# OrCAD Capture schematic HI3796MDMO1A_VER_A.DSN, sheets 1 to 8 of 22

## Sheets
1 SHEET_01
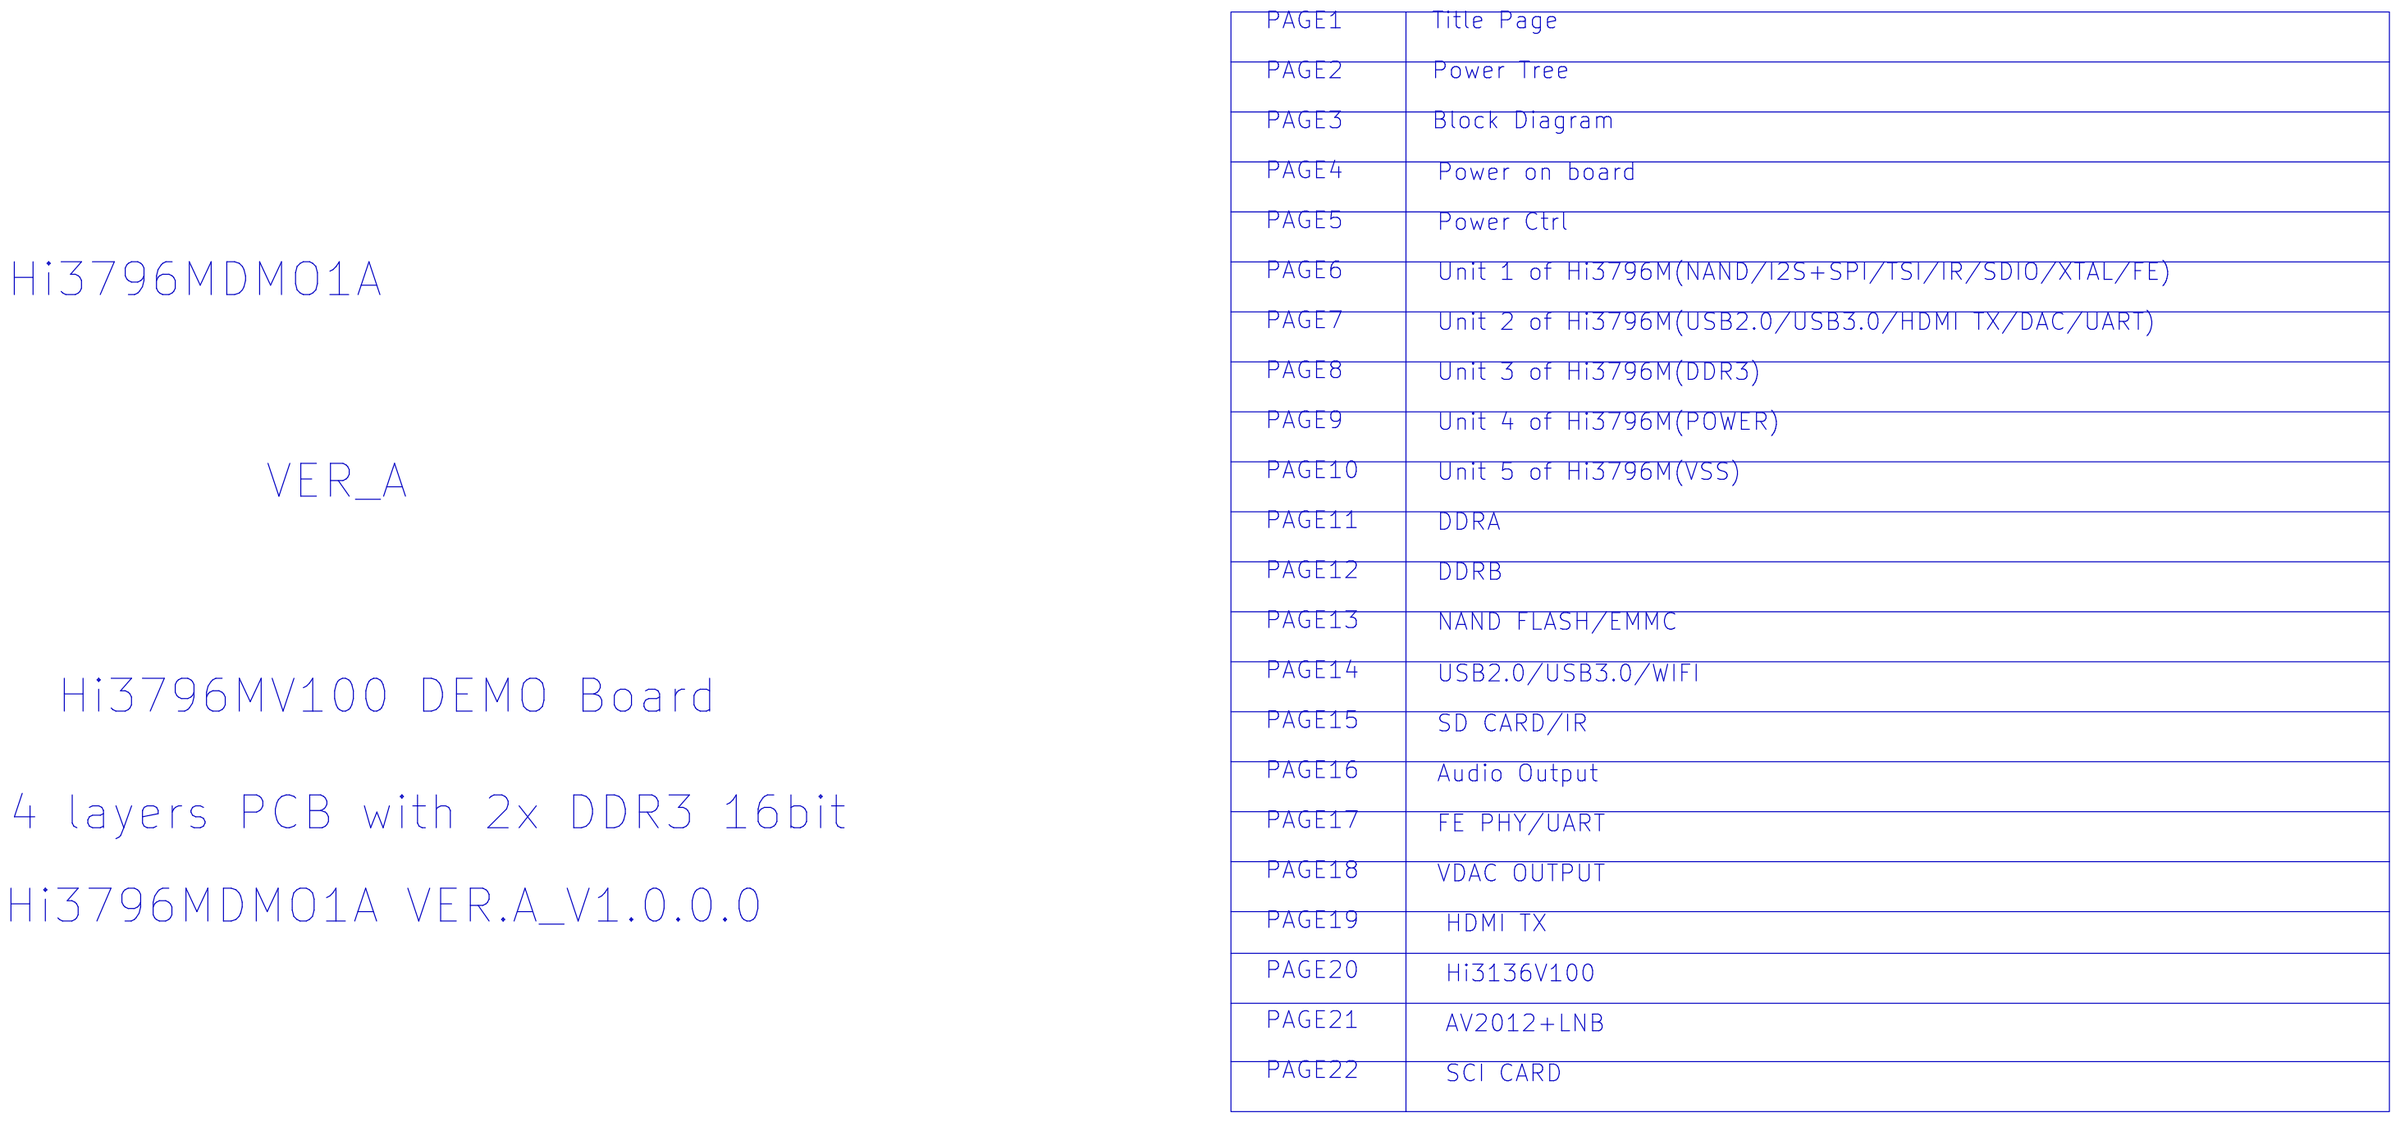
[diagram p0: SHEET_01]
2 SHEET_02
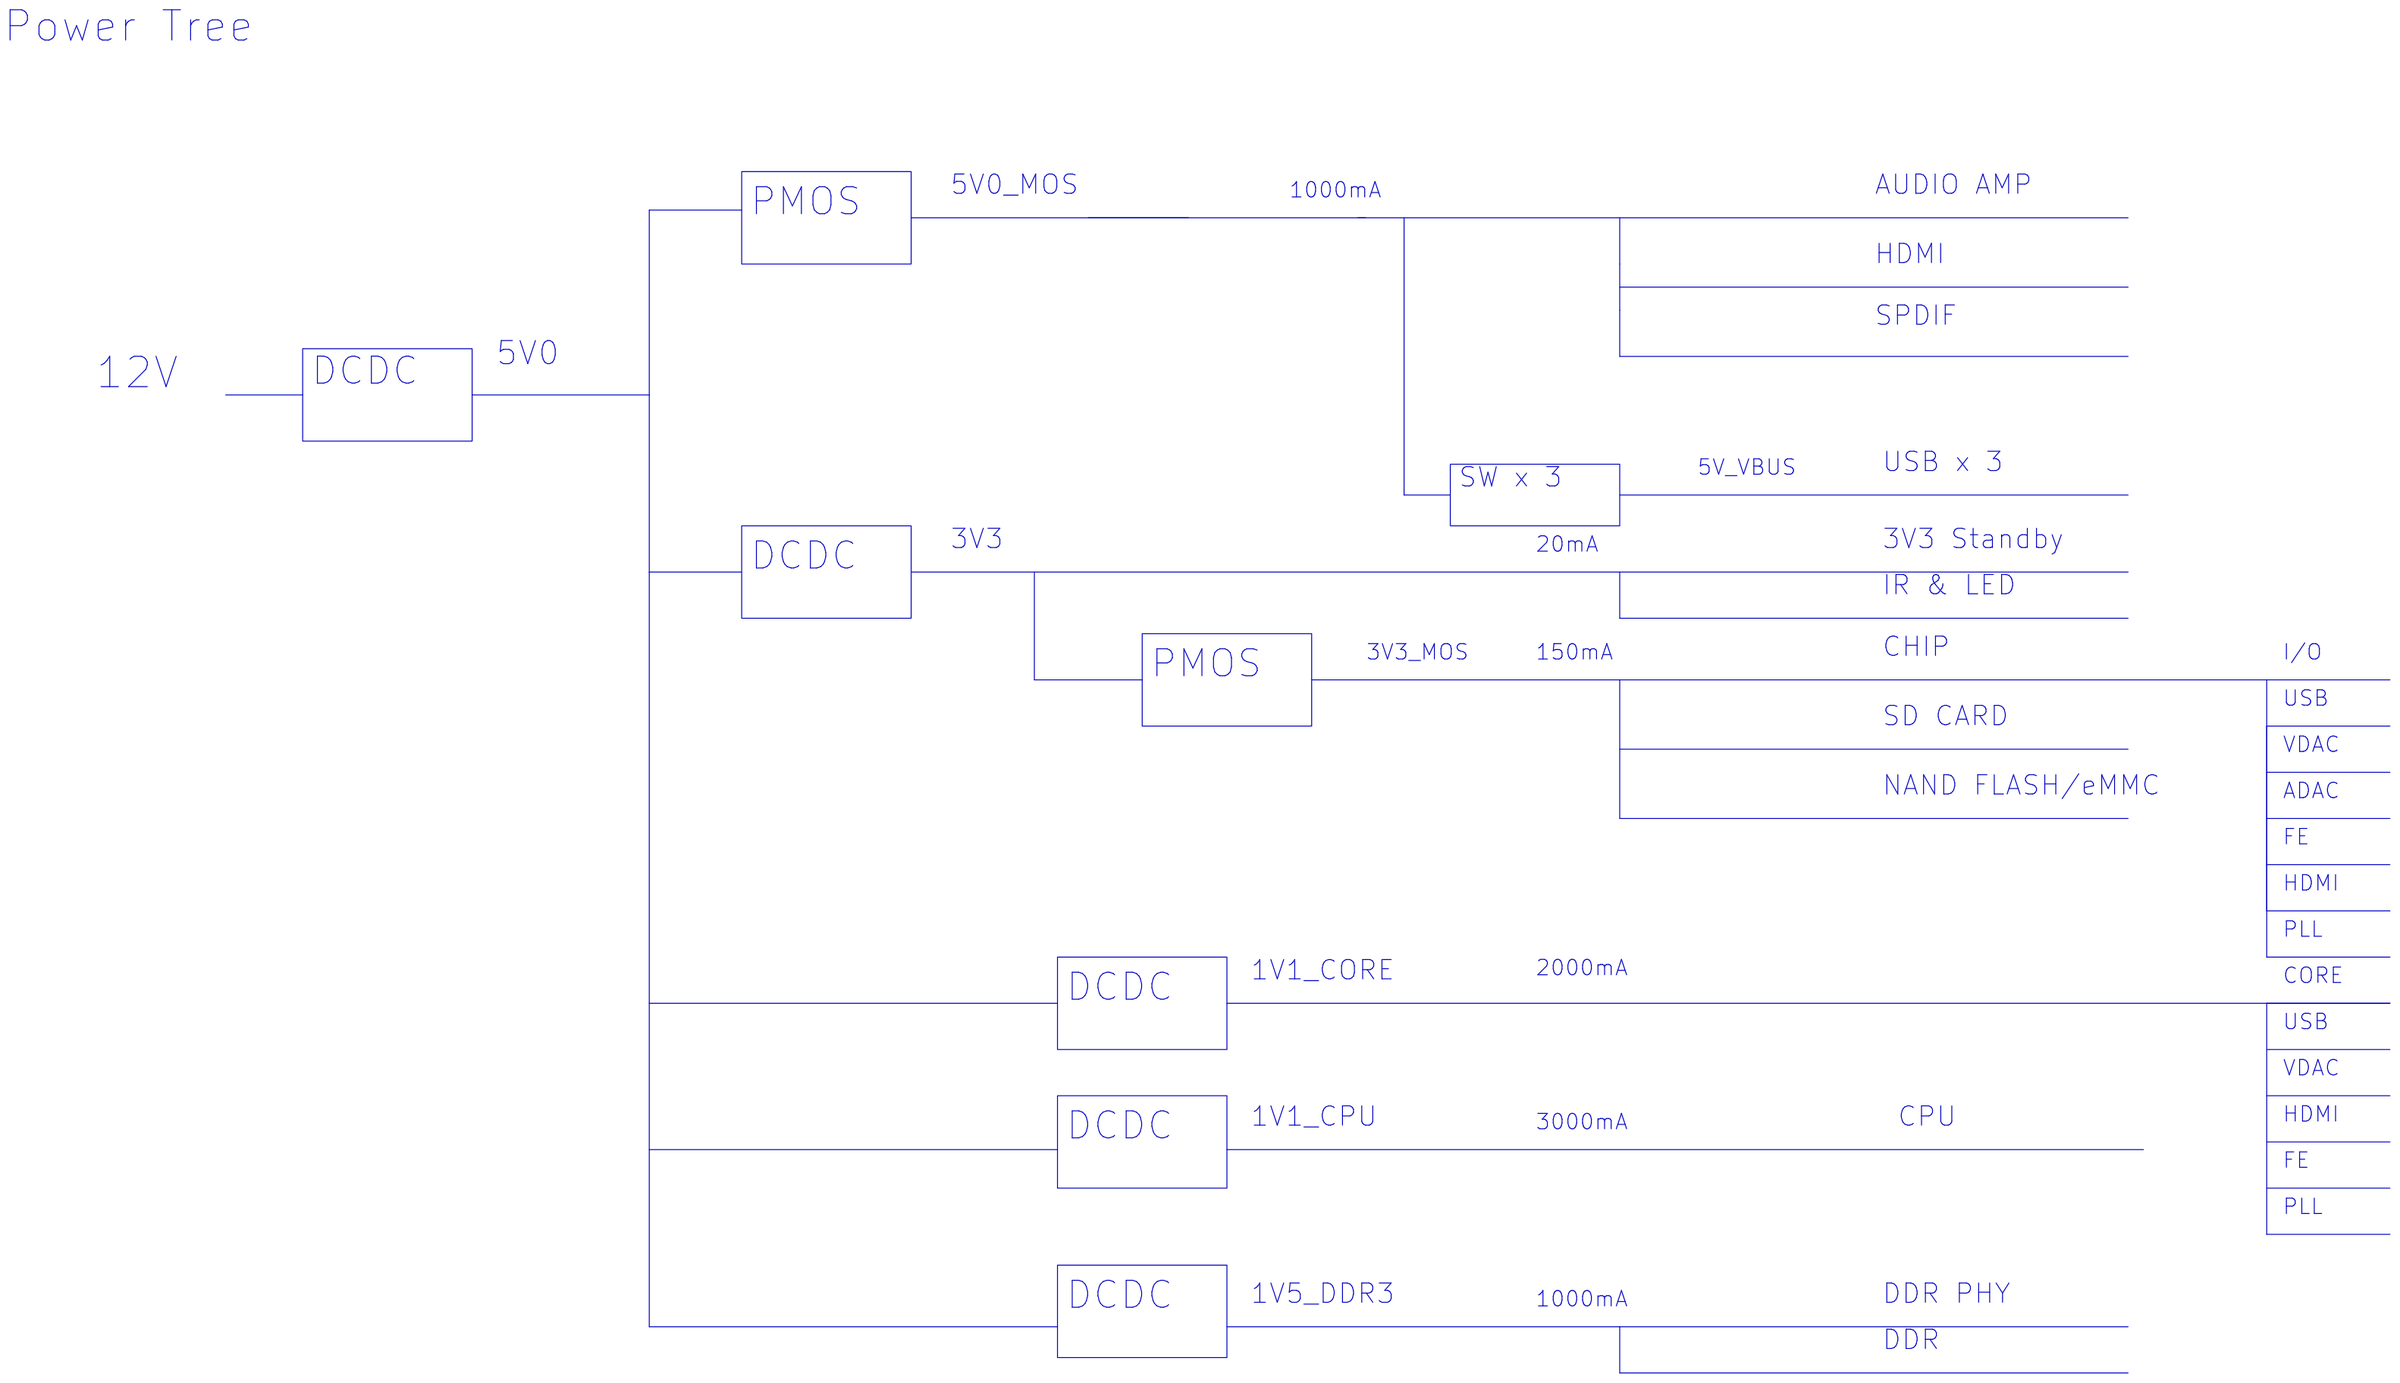
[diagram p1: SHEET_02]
3 SHEET_03: size B
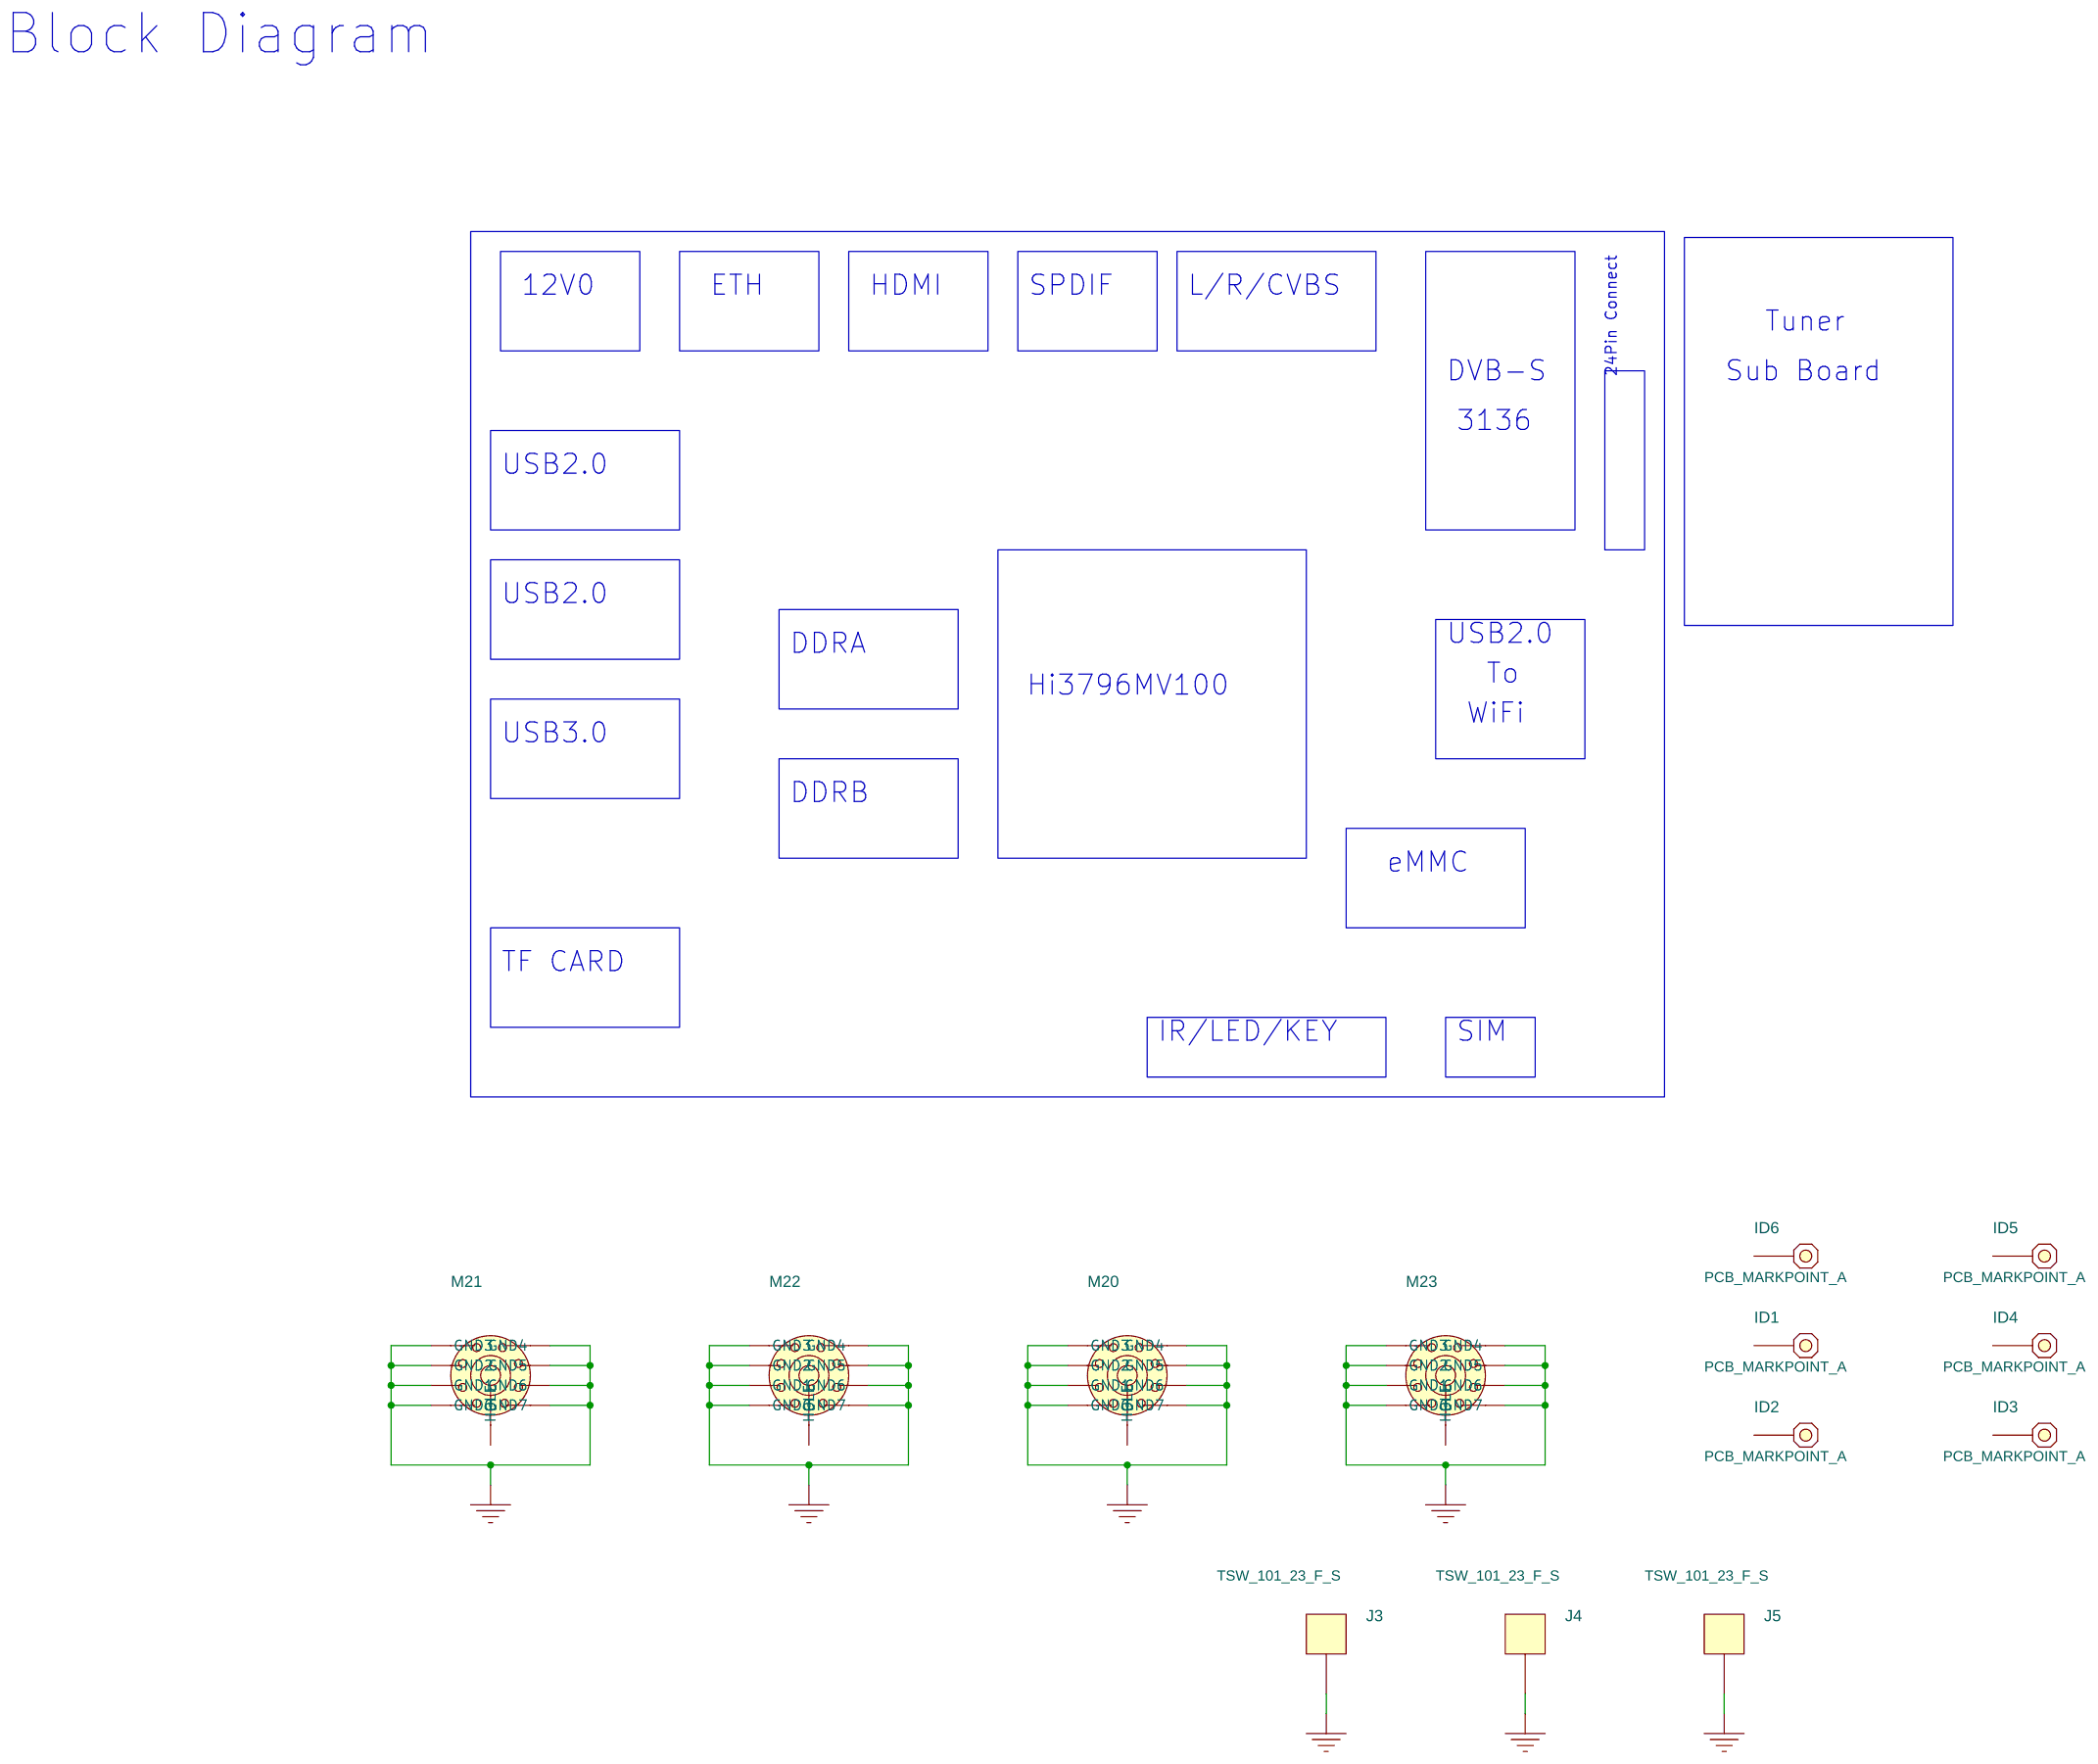
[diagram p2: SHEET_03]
4 SHEET_04: size Custom
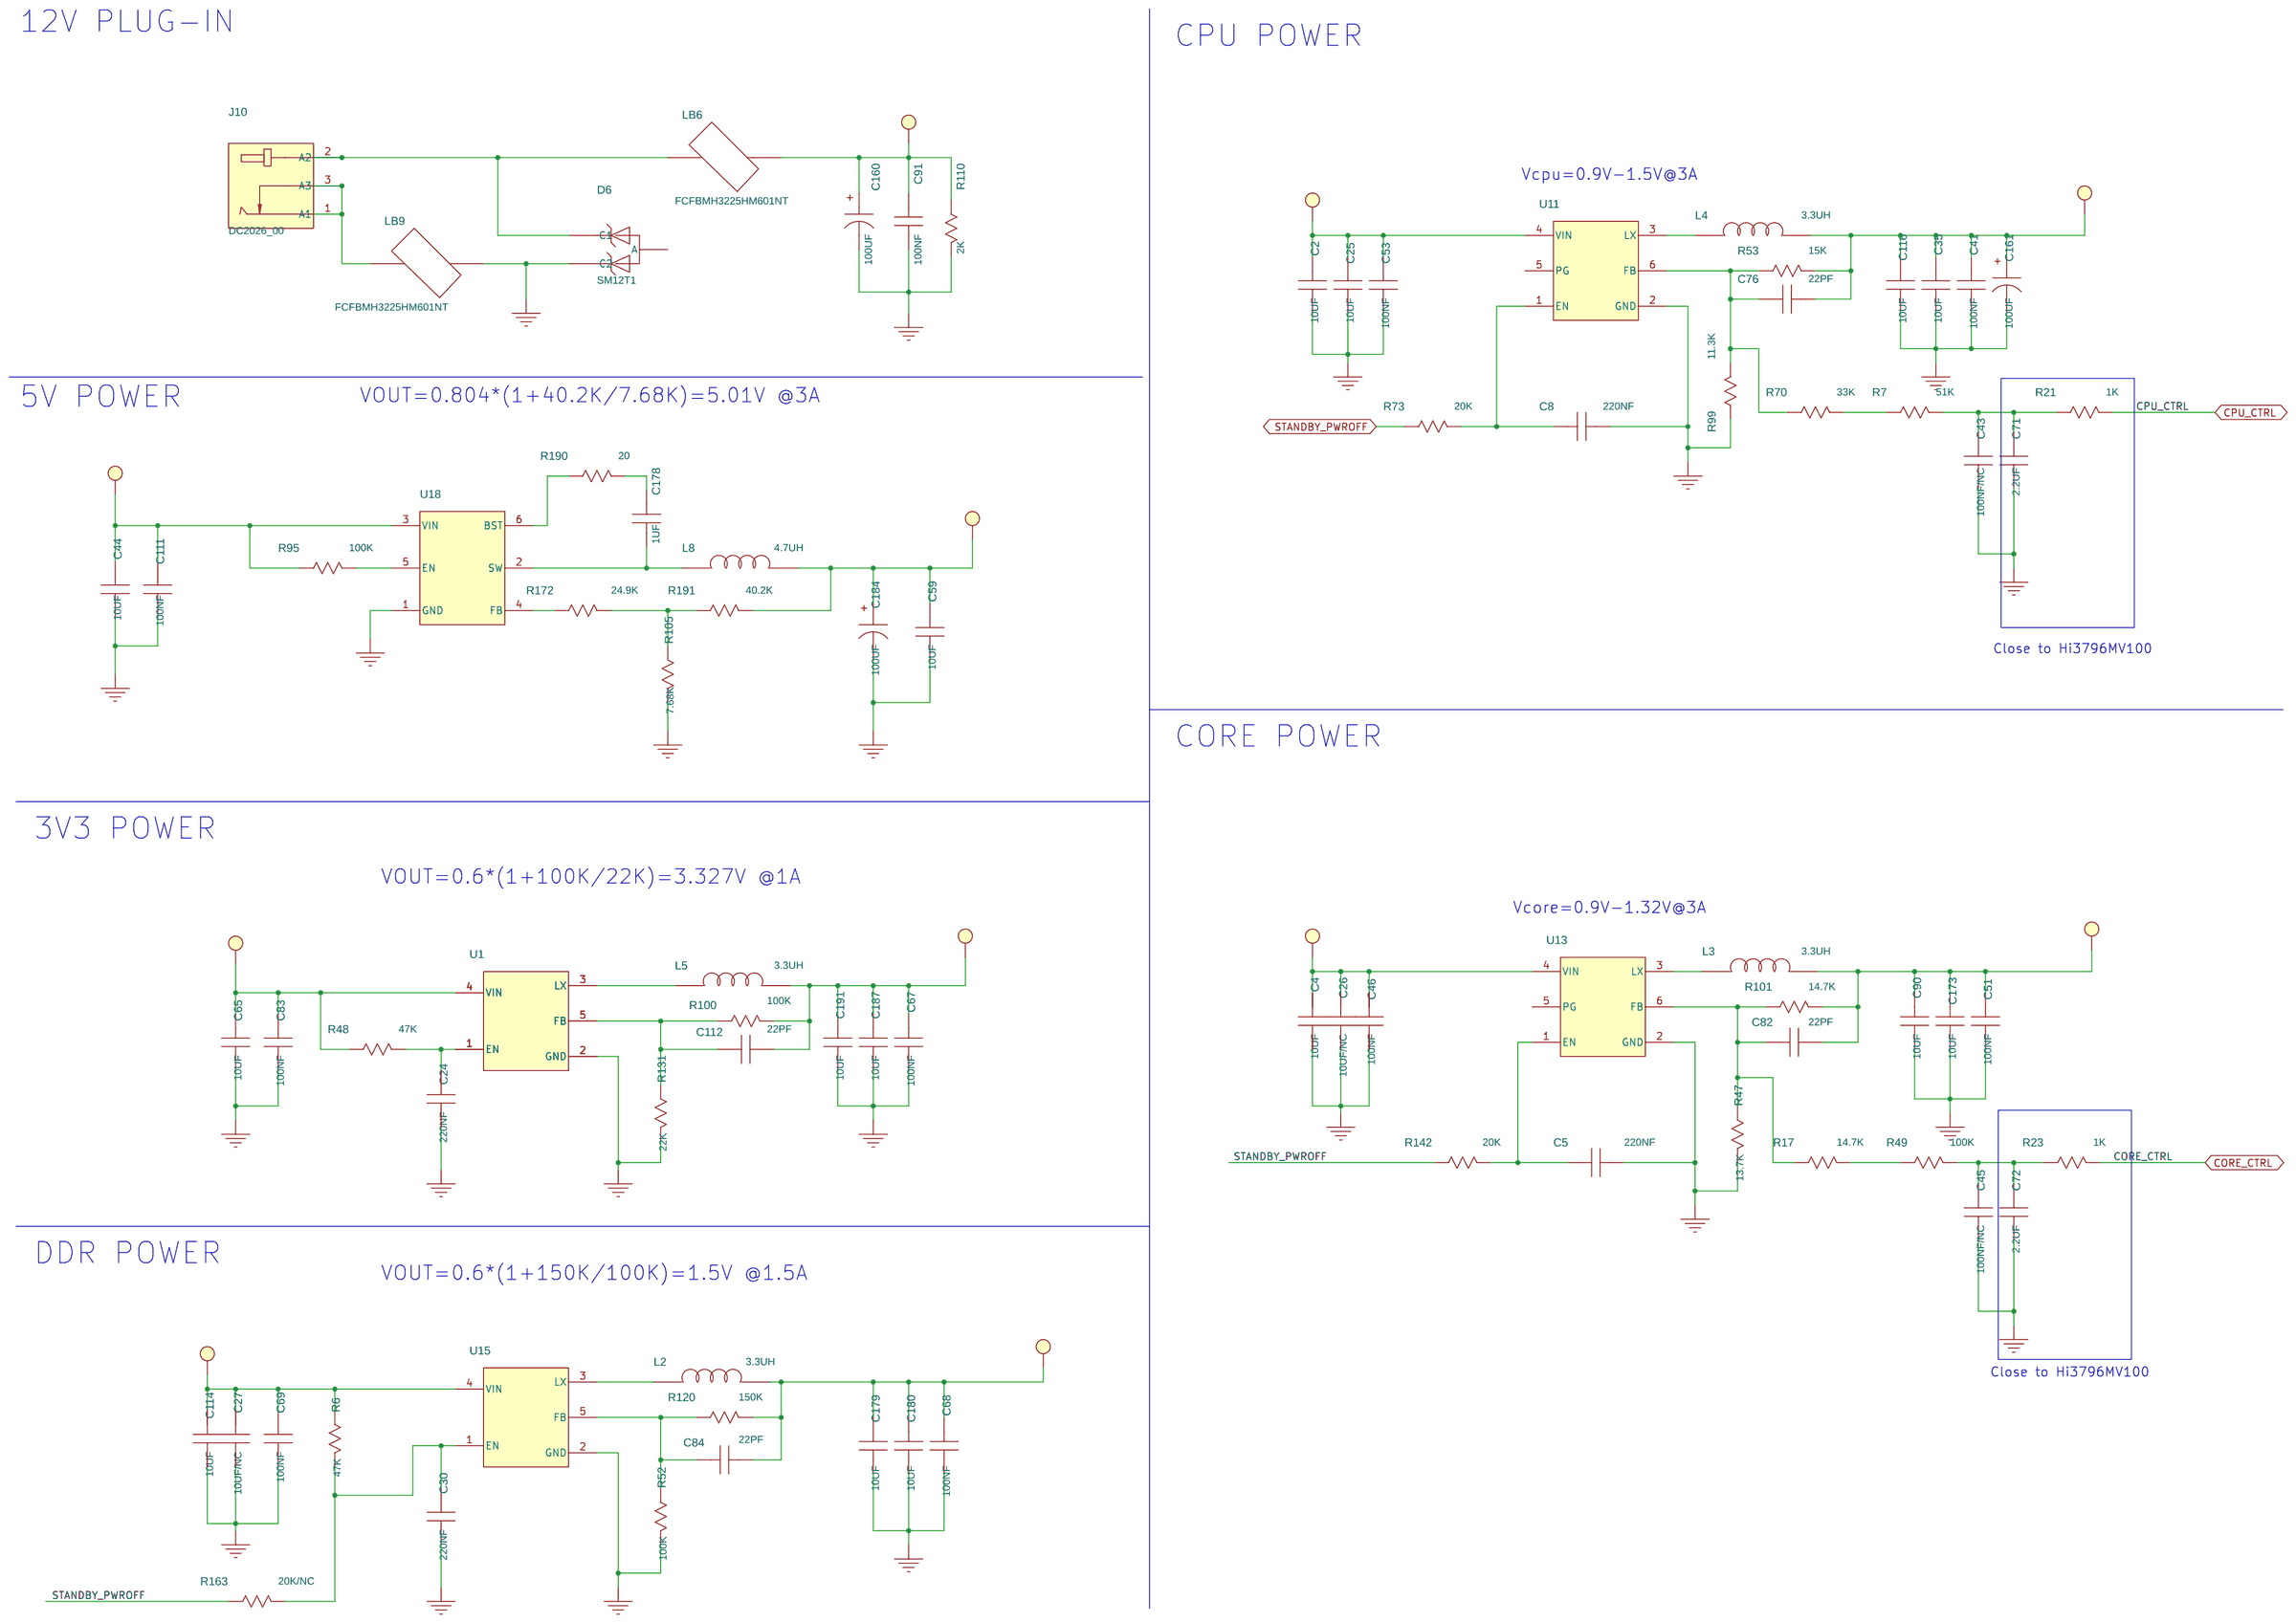
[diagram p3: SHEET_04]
5 SHEET_05: size B
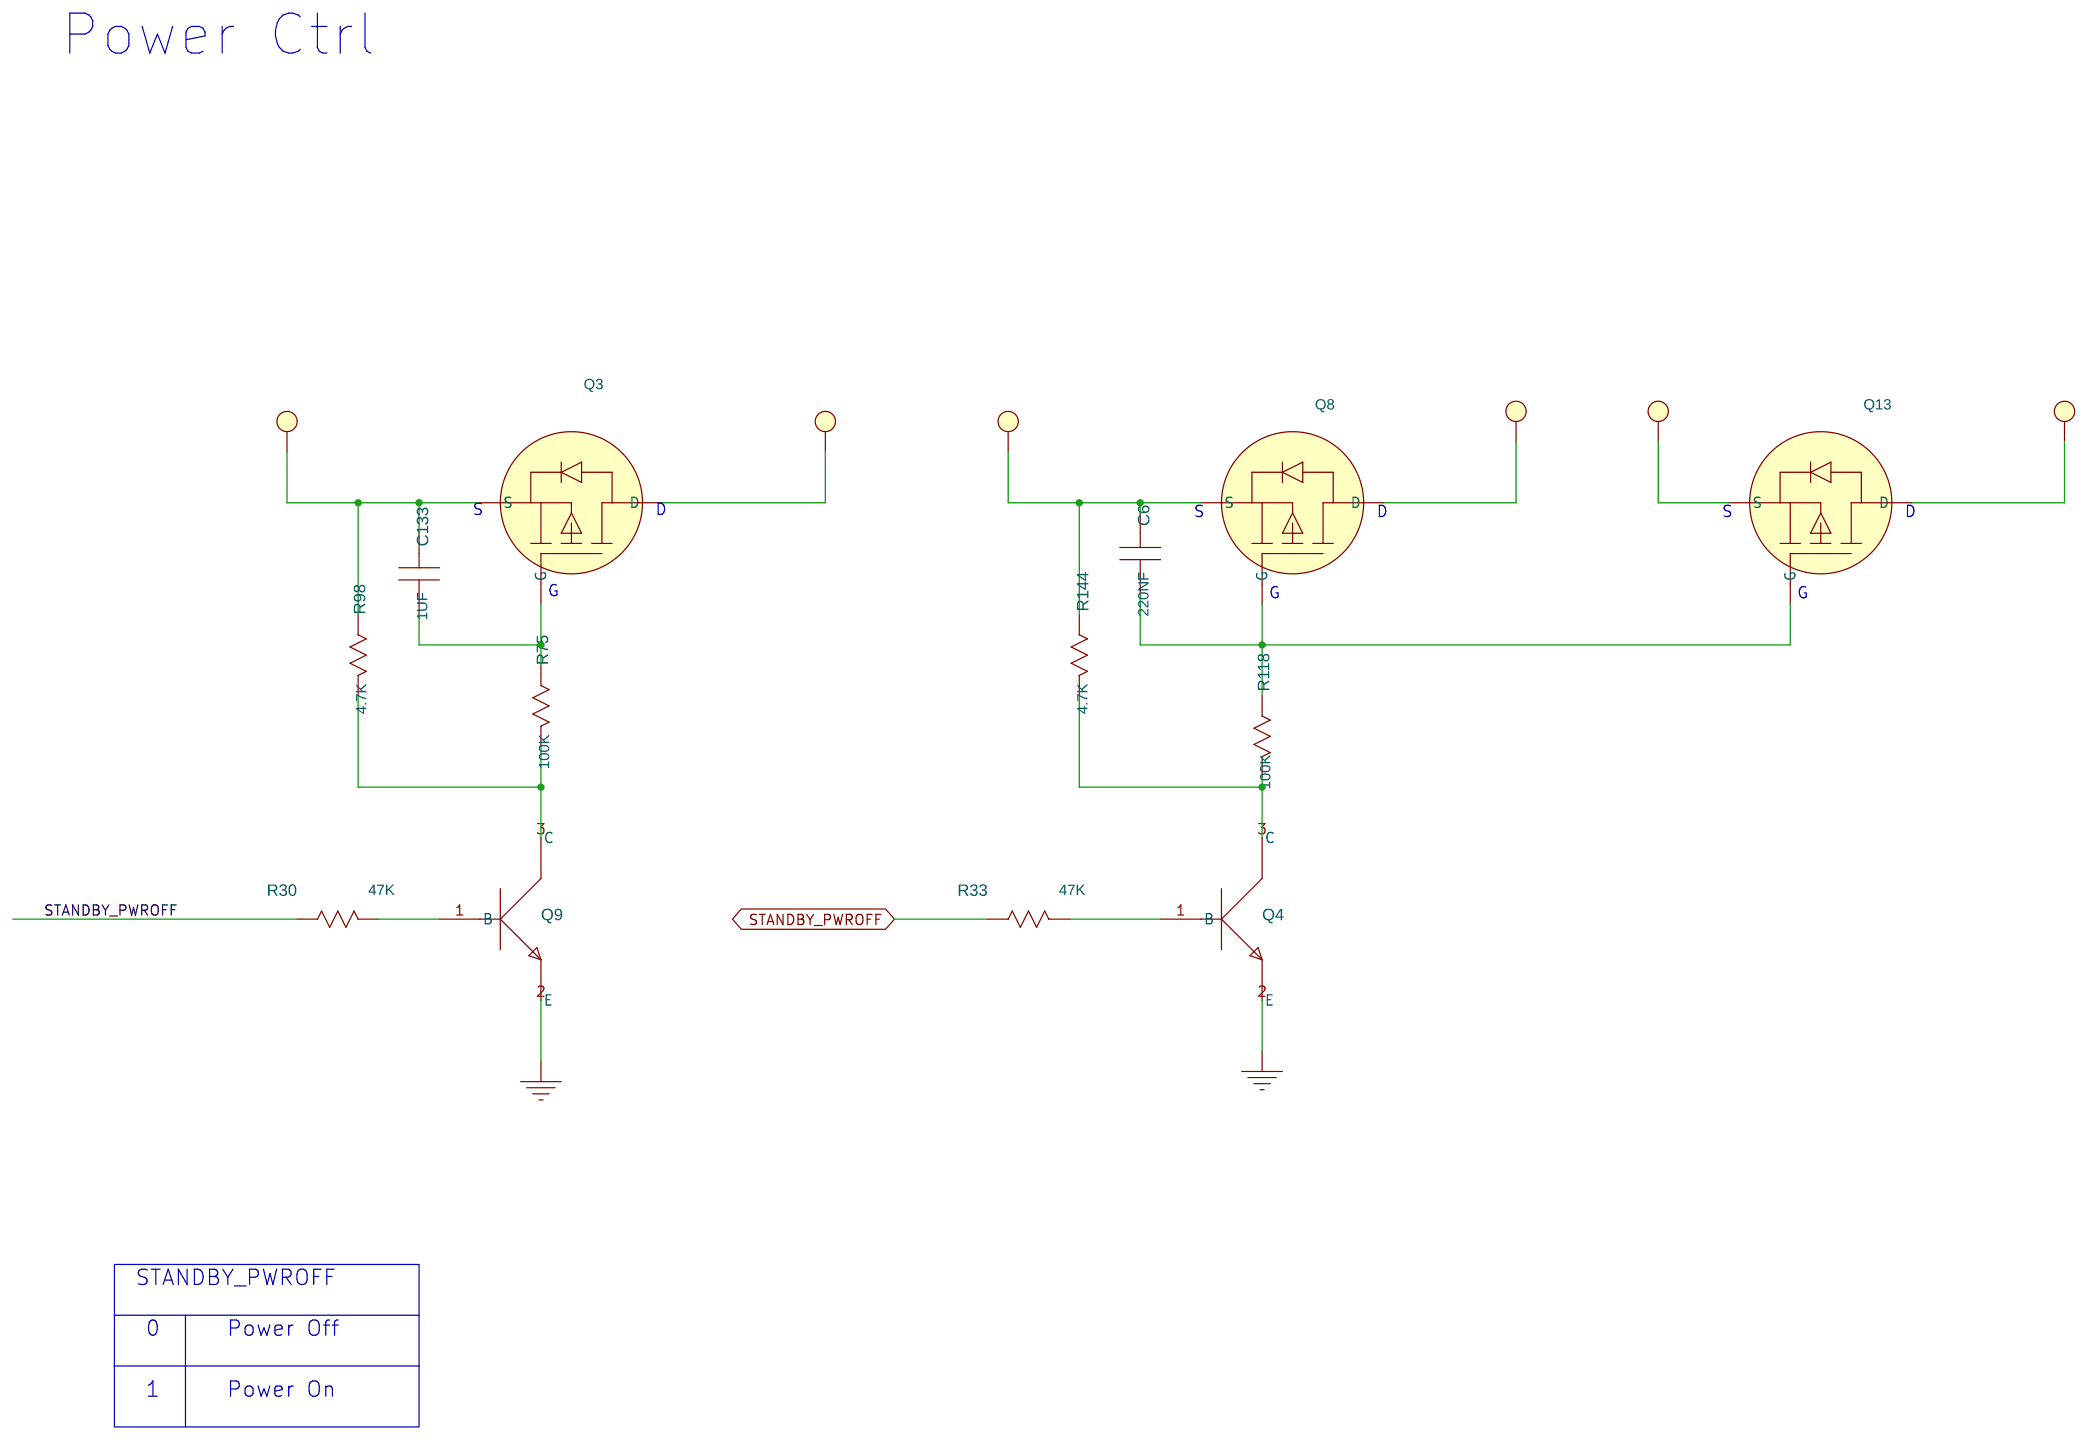
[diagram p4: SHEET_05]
6 SHEET_06: size Custom
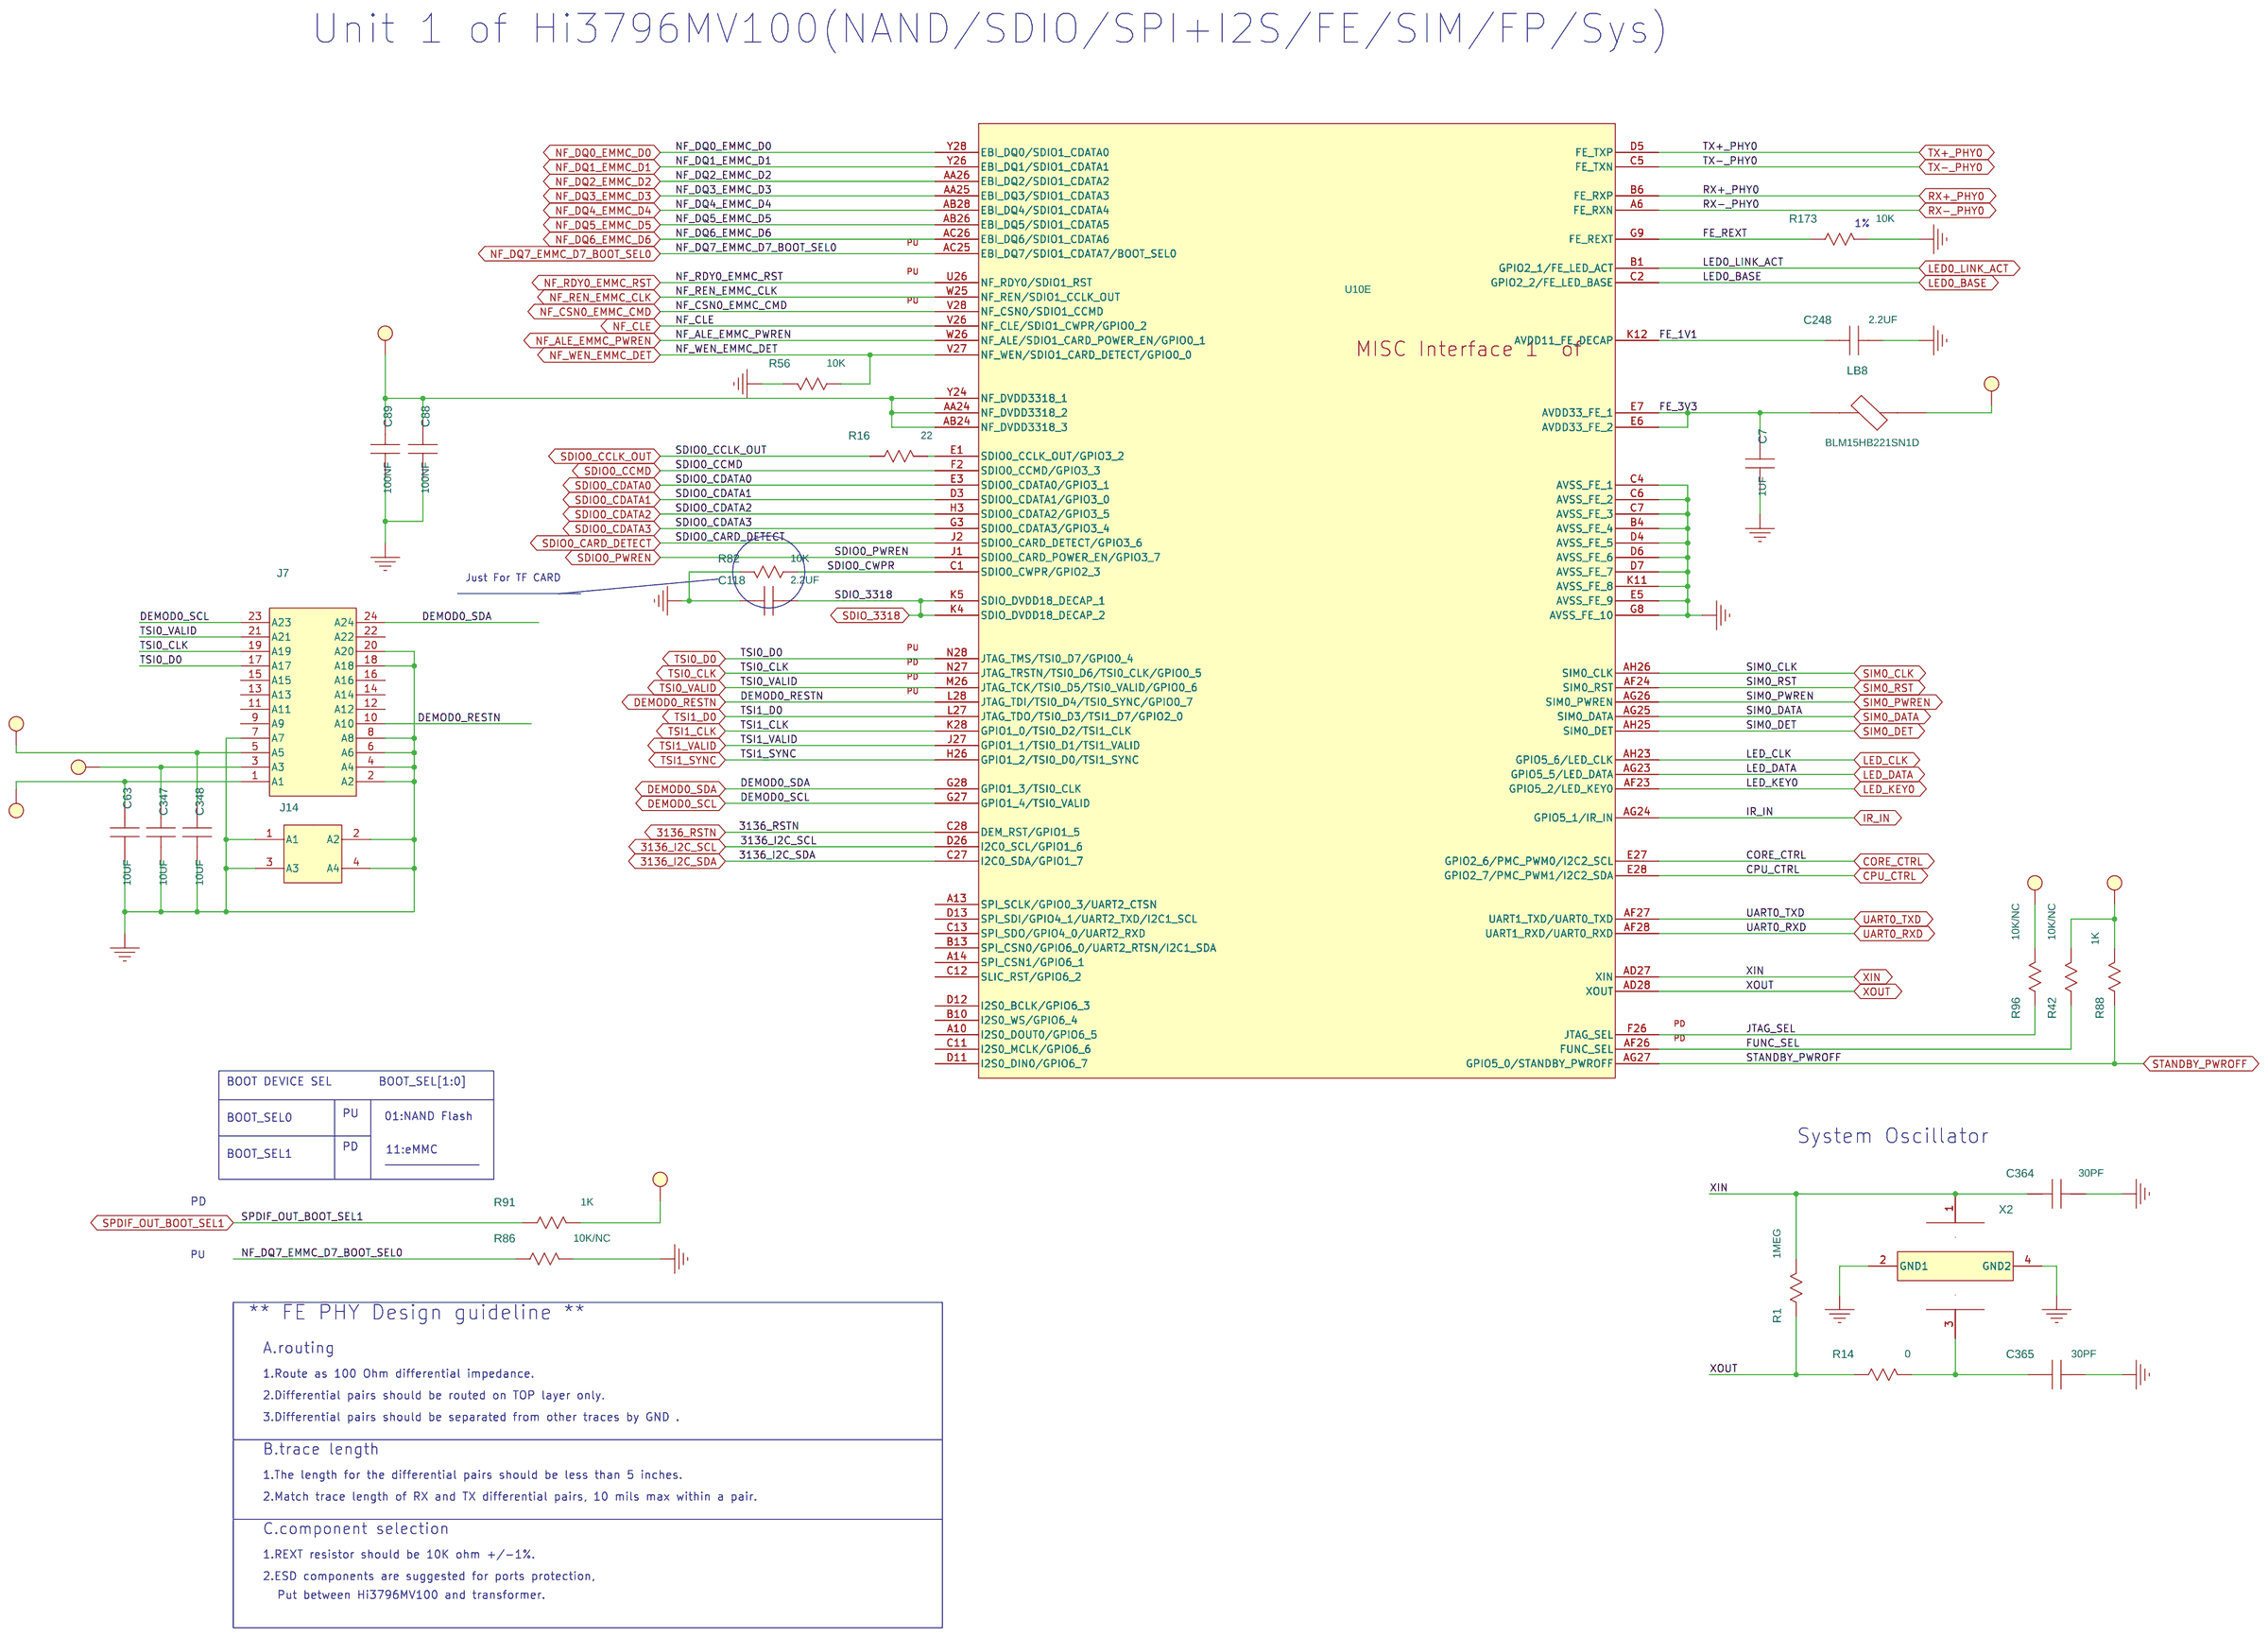
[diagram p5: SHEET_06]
7 SHEET_07: size Custom
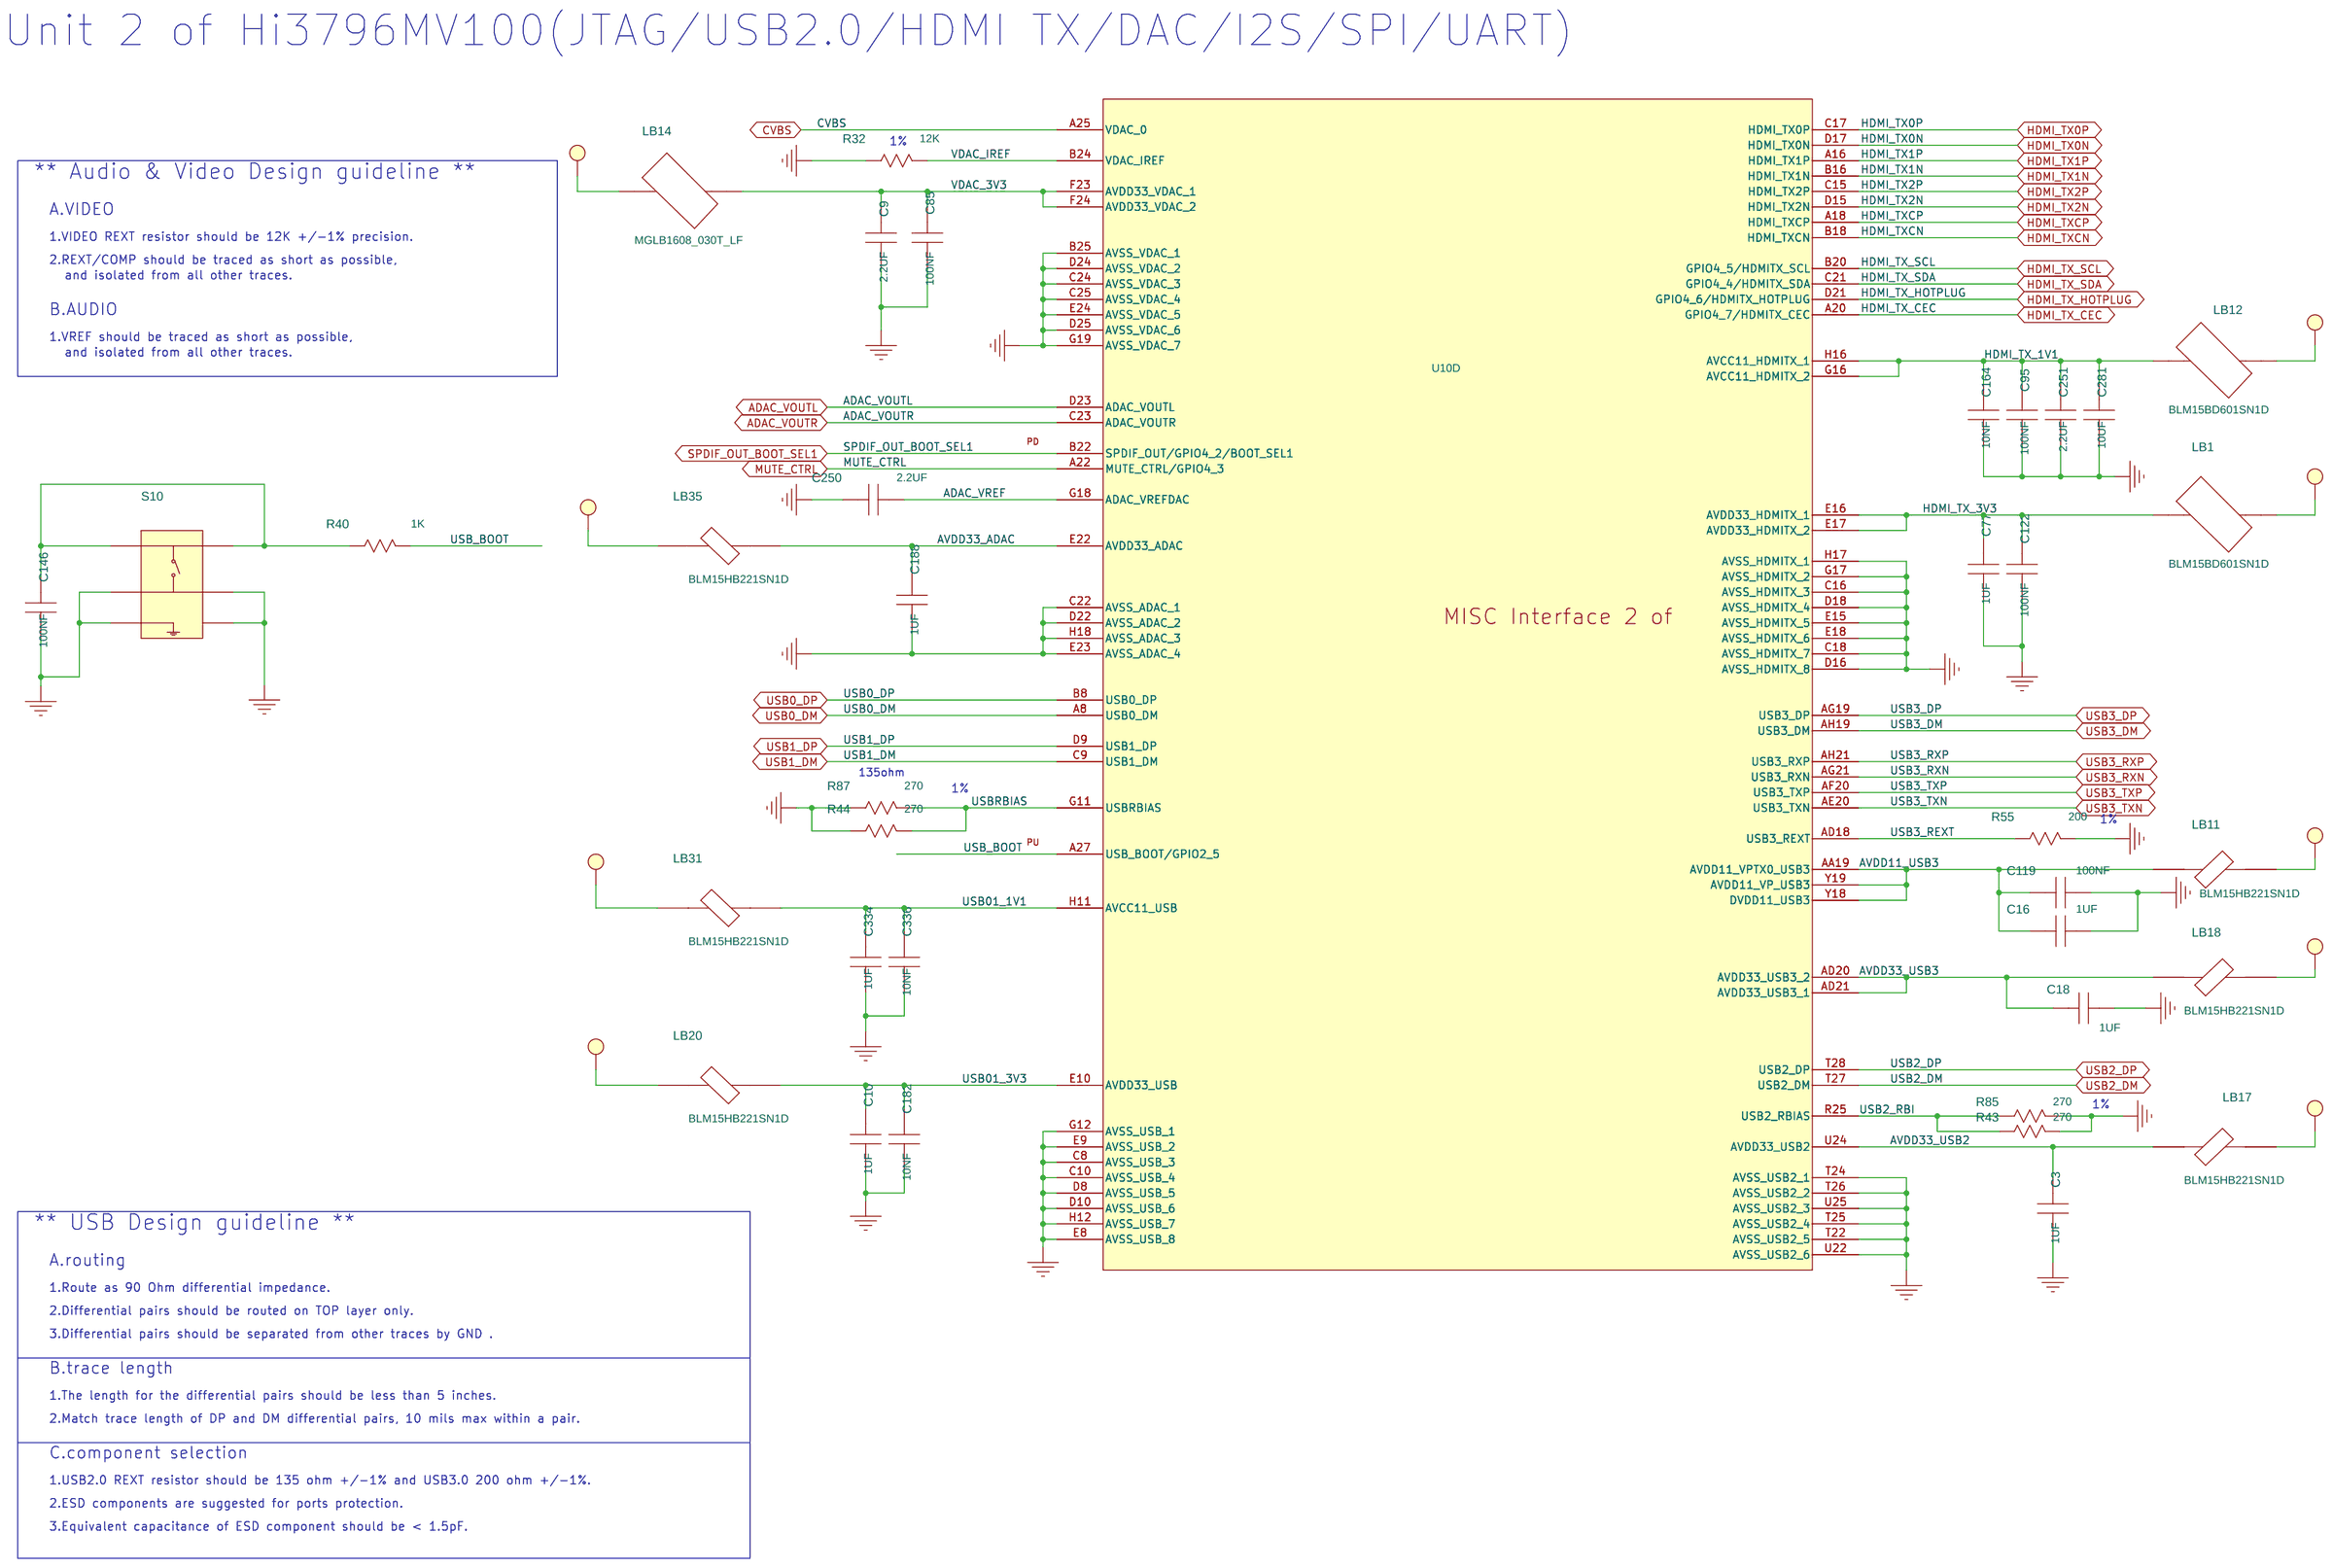
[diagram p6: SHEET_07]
8 SHEET_08: size Custom
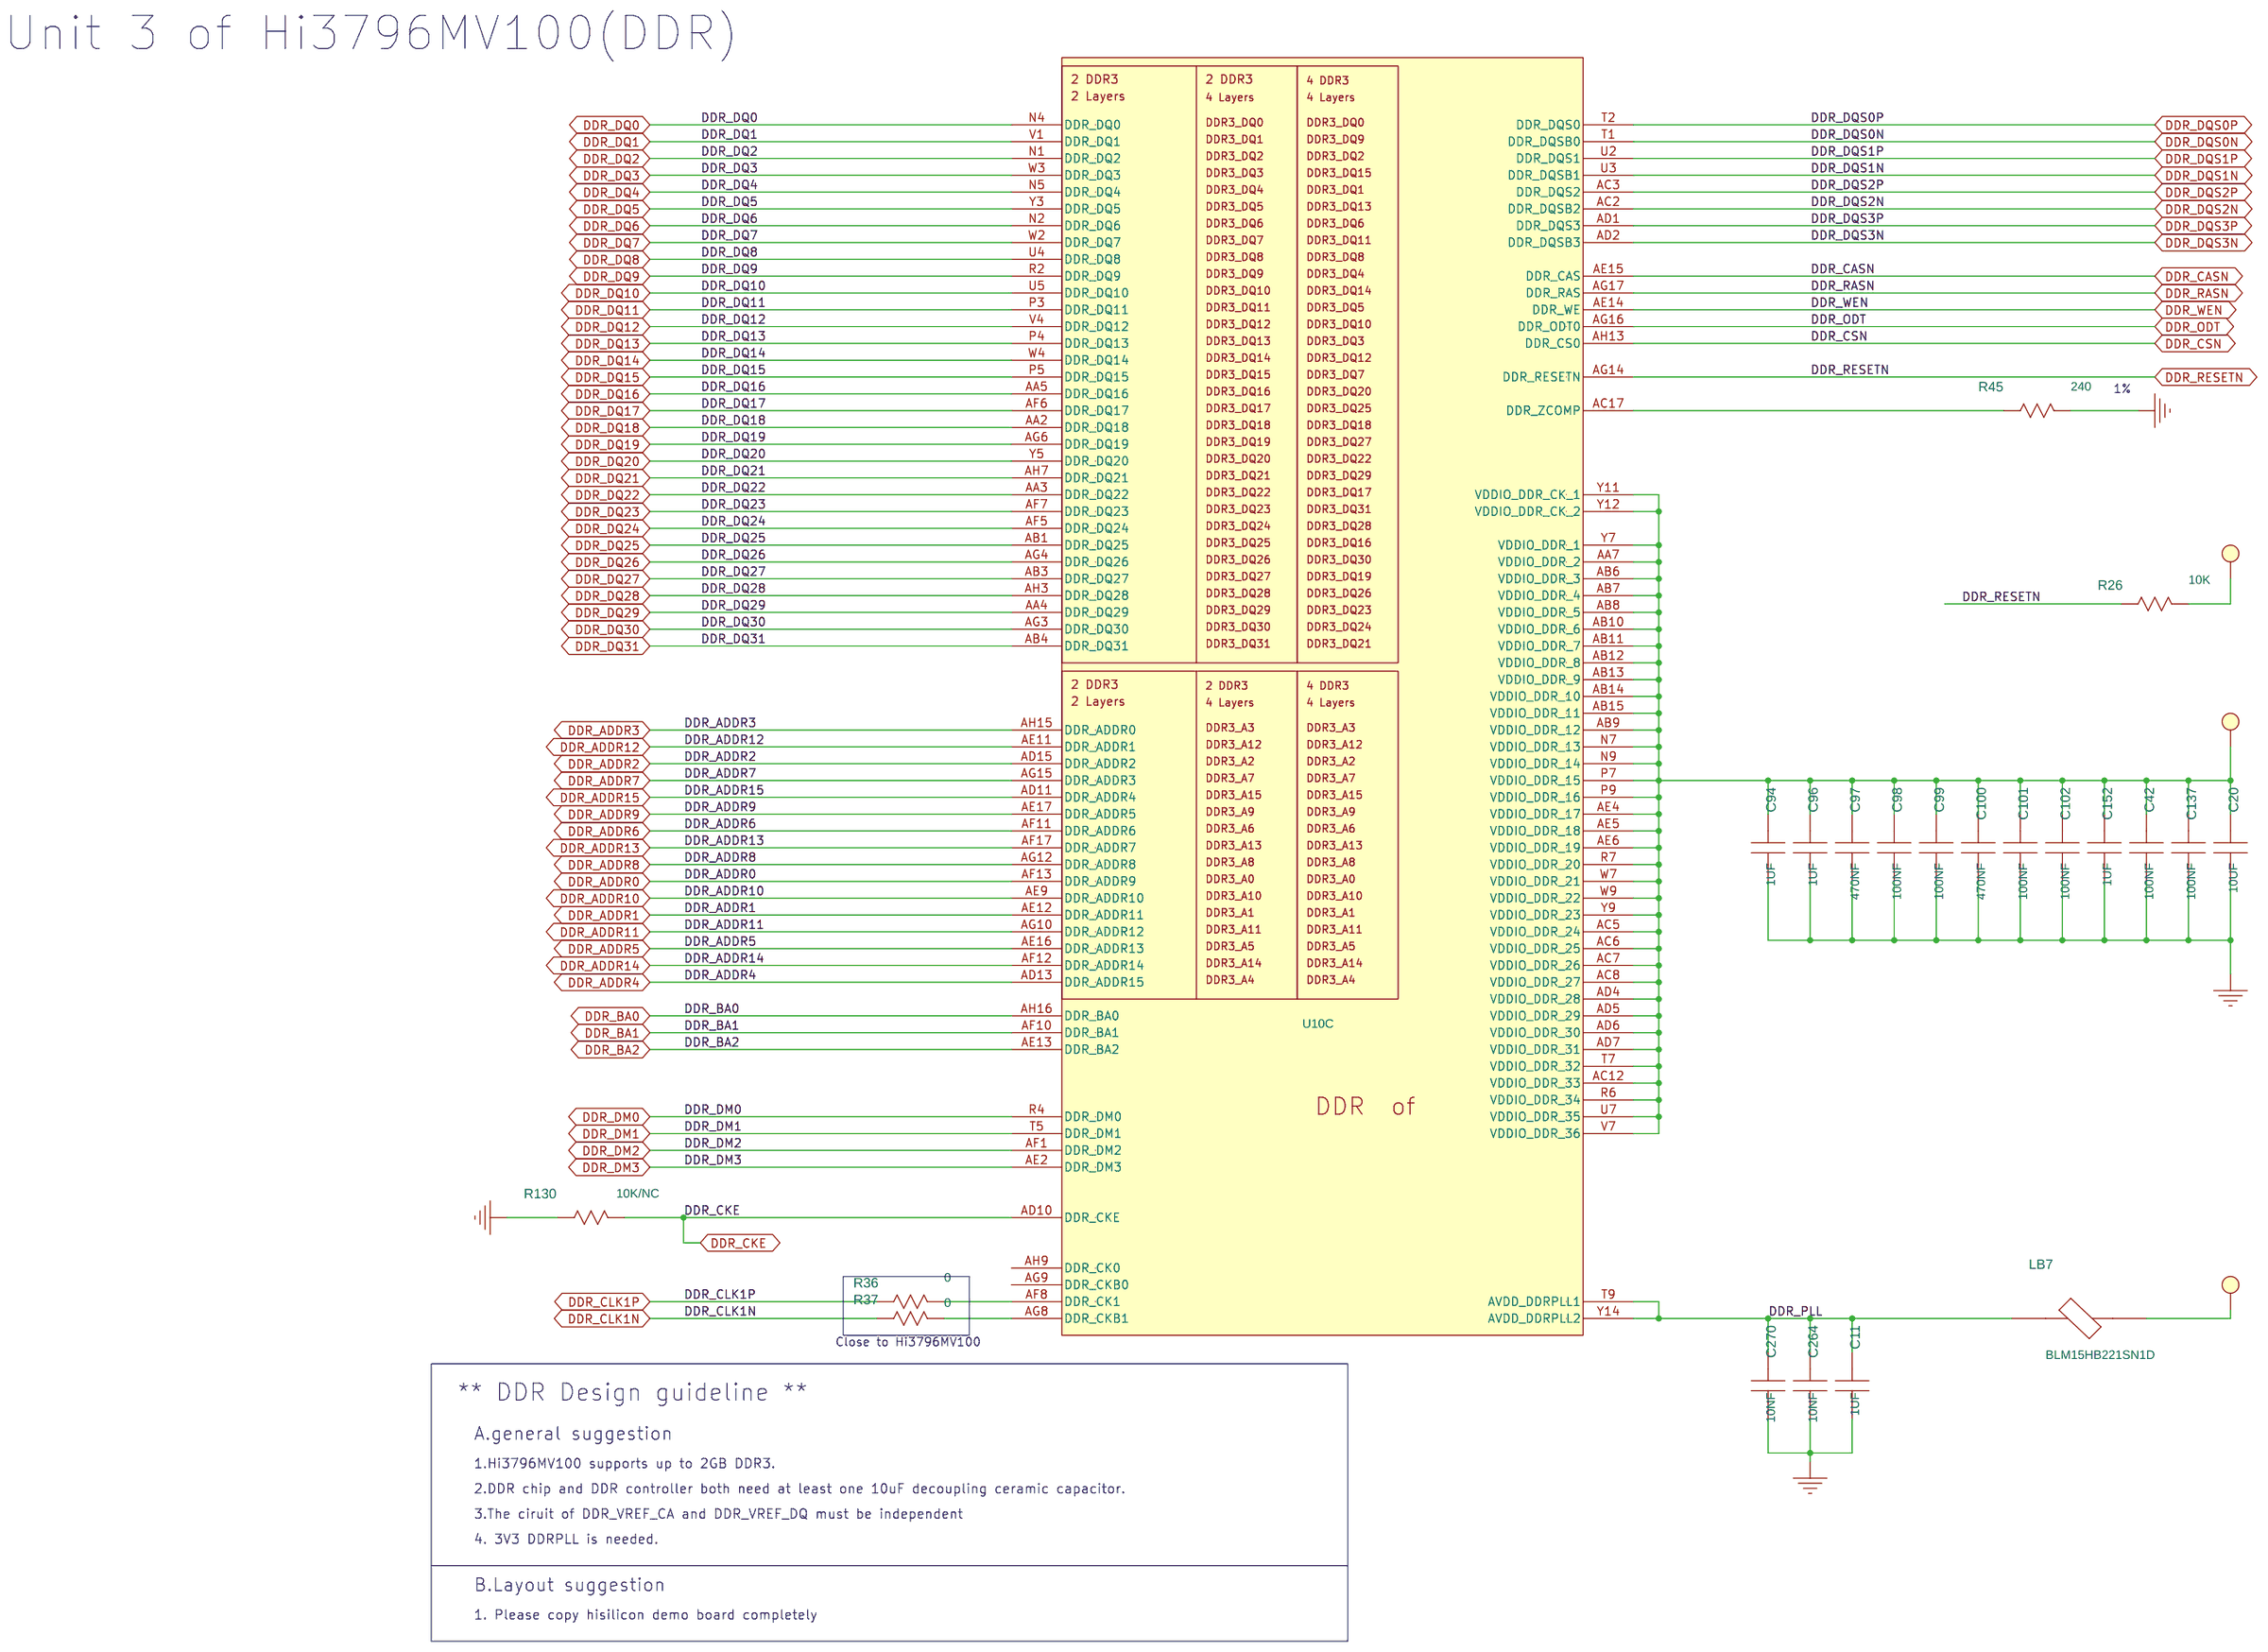
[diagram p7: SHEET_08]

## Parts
sheet SHEET_03
ID1  ID-BOARD  [ID-BOARD]
ID2  ID-BOARD  [ID-BOARD]
ID3  ID-BOARD  [ID-BOARD]
ID4  ID-BOARD  [ID-BOARD]
ID5  ID-BOARD  [ID-BOARD]
ID6  ID-BOARD  [ID-BOARD]
J3  NC  [SIP-1P]
J4  NC  [SIP-1P]
J5  NC  [SIP-1P]
M20  HOLE-8STARS  [HOLE138-8STAR]
M21  HOLE-8STARS  [HOLE138-8STAR]
M22  HOLE-8STARS  [HOLE138-8STAR]
M23  HOLE-8STARS  [HOLE138-8STAR]
sheet SHEET_04
C2  10UF  [SC0805]
C4  10UF  [SC0805]
C5  220NF  [SC0402]
C8  220NF  [SC0402]
C24  220NF  [SC0402]
C25  10UF  [SC0805]
C26  10UF/NC  [SC0805]
C27  10UF/NC  [SC0805]
C30  220NF  [SC0402]
C35  10UF  [SC0603]
C41  100NF  [SC0402]
C43  100NF/NC  [SC0402]
C44  10UF  [SC0805]
C45  100NF/NC  [SC0402]
C46  100NF  [SC0402]
C51  100NF  [SC0402]
C53  100NF  [SC0402]
C59  10UF  [SC0805]
C65  10UF  [SC0805]
C67  100NF  [SC0402]
C68  100NF  [SC0402]
C69  100NF  [SC0402]
C71  2.2UF  [SC0603]
C72  2.2UF  [SC0603]
C76  22PF  [SC0402]
C82  22PF  [SC0402]
C83  100NF  [SC0402]
C84  22PF  [SC0402]
C90  10UF  [SC0603]
C91  100NF  [SC0603]
C111  100NF  [SC0603]
C112  22PF  [SC0402]
C114  10UF  [SC0805]
C116  10UF  [SC0603]
C160  100UF  [SAC6666]
C161  100UF  [SAC6666]
C173  10UF  [SC0603]
C178  1UF  [SC0402]
C179  10UF  [SC0603]
C180  10UF  [SC0603]
C184  100UF  [SAC6666]
C187  10UF  [SC0603]
C191  10UF  [SC0603]
D6  D2-3_D  [SOT23]
J10  PWC3_A  [PWC0103-M-N]
L2  3.3UH  [SWPA4030S]
L3  3.3UH  [SWPA4030S]
L4  3.3UH  [SWPA4030S]
L5  3.3UH  [SWPA4030S]
L8  4.7UH  [SWPA5040S]
LB6  LB  [SL1210]
LB9  LB  [SL1210]
R6  47K  [SR0402]
R7  51K  [SR0402]
R17  14.7K  [SR0402]
R21  1K  [SR0402]
R23  1K  [SR0402]
R47  13.7K  [SR0402]
R48  47K  [SR0402]
R49  100K  [SR0402]
R52  100K  [SR0402]
R53  15K  [SR0402]
R70  33K  [SR0402]
R73  20K  [SR0402]
R95  100K  [SR0402]
R99  11.3K  [SR0402]
R100  100K  [SR0402]
R101  14.7K  [SR0402]
R105  7.68K  [SR0603]
R110  2K  [SR0603]
R120  150K  [SR0402]
R131  22K  [SR0402]
R142  20K  [SR0402]
R163  20K/NC  [SR0402]
R172  24.9K  [SR0402]
R190  20  [SR0402]
R191  40.2K  [SR0603]
U1  SY8009A  [SOT23_5]
U11  SY8032  [SOT23_6]
U13  SY8032  [SOT23_6]
U15  SY8009A  [SOT23_5]
U18  MP1470_1471A  [SOT23_6]
sheet SHEET_05
C6  220NF  [SC0603]
C133  1UF  [SC0603]
Q3  PMOS-GSD  [SOT23]
Q4  NPN-BEC  [SOT23]
Q8  PMOS-GSD  [SOT23]
Q9  NPN-BEC  [SOT23]
Q13  PMOS-GSD  [SOT23]
R30  47K  [SR0402]
R33  47K  [SR0402]
R75  100K  [SR0402]
R98  4.7K  [SR0402]
R118  100K  [SR0402]
R144  4.7K  [SR0402]
sheet SHEET_06
C7  1UF  [SC0402]
C63  10UF  [SC0805]
C88  100NF  [SC0402]
C89  100NF  [SC0402]
C118  2.2UF  [HSC0402]
C248  2.2UF  [HSC0402]
C347  10UF  [SC0805]
C348  10UF  [SC0805]
C364  30PF  [SC0402]
C365  30PF  [SC0402]
J7  WBC2X12  [HEAD0212-RF-SUB]
J14  HEAD2X2  [HEAD0202-RF]
LB8  LB  [SL0402]
R1  1MEG  [SR0402]
R14  0  [SR0402]
R16  22  [SR0402]
R42  10K/NC  [SR0402]
R56  10K  [SR0402]
R82  10K  [SR0402]
R86  10K/NC  [SR0402]
R88  1K  [SR0402]
R91  1K  [SR0402]
R96  10K/NC  [SR0402]
R173  10K  [SR0402]
X2  24MHZ  [X288]
sheet SHEET_07
C3  1UF  [SC0402]
C9  2.2UF  [HSC0402]
C10  1UF  [SC0402]
C16  1UF  [SC0402]
C18  1UF  [SC0402]
C77  1UF  [SC0402]
C85  100NF  [SC0402]
C95  100NF  [SC0402]
C119  100NF  [SC0402]
C122  100NF  [SC0402]
C146  100NF  [SC0402]
C164  10NF  [SC0402]
C182  10NF  [SC0402]
C188  1UF  [SC0402]
C250  2.2UF  [HSC0402]
C251  2.2UF  [HSC0402]
C281  10UF  [SC0603]
C334  1UF  [SC0402]
C336  10NF  [SC0402]
LB1  LB  [SL0402]
LB11  LB  [SL0402]
LB12  LB  [SL0402]
LB14  LB  [SL0603]
LB17  LB  [SL0402]
LB18  LB  [SL0402]
LB20  LB  [SL0402]
LB31  LB  [SL0402]
LB35  LB  [SL0402]
R32  12K  [SR0402]
R40  1K  [SR0402]
R43  270  [SR0402]
R44  270  [SR0402]
R55  200  [SR0402]
R85  270  [SR0402]
R87  270  [SR0402]
S10  MSW-6A  [SPSW6-T]
sheet SHEET_08
C11  1UF  [SC0402]
C20  10UF  [SC0805]
C42  100NF  [SC0402]
C94  1UF  [SC0402]
C96  1UF  [SC0402]
C97  470NF  [SC0402]
C98  100NF  [SC0402]
C99  100NF  [SC0402]
C100  470NF  [SC0402]
C101  100NF  [SC0402]
C102  100NF  [SC0402]
C137  100NF  [SC0402]
C152  1UF  [SC0402]
C264  10NF  [SC0402]
C270  10NF  [SC0402]
LB7  LB  [SL0402]
R26  10K  [SR0402]
R36  0  [SR0402]
R37  0  [SR0402]
R45  240  [SR0402]
R130  10K/NC  [SR0402]
sheet SHEET_10
U10  HI3796MV100  [PBGA573-32-27X27]  (sections A,B,C,D,E,F)

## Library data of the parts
ID1-ID6 = ID-BOARD: %195%%232%%202%%246%: PCB-MARK点ID-BOARD，亮铜直径40MIL，阻焊开窗直径80MIL，MARK点大小120MIL。; DEVICE: PCB_MARKPOINT_A
J3-J5 = SIP1: %195%%232%%202%%246%: 插针-普通方脚插针-1PIN-单排-直式-5.84MM-2.92MM-2.54MM-THT; %208%%161%%192%%224%%195%%251%%179%%198%: 插针; CODE: 14050101; DEVICE: TSW_101_23_F_S
M20-M23 = HOLE-8STARS: %195%%232%%202%%246%: M3螺钉(推荐使用)，对应138MIL星月孔，适用于过波峰焊设计。; DEVICE: 138MIL_STAR_HOLE_APPLY_TO_M3
C2 C4 C25-C27 C44 C59 C63 C65 C114 C347 C348 = C_0: %182%%238%%182%%168%%185%%164%%215%%247%%181%%231%%209%%185%(V): 25; %195%%232%%202%%246%: SMD陶瓷电容-25V-10000NF-+/-20%-X5R-0805; %208%%161%%192%%224%%195%%251%%179%%198%: SMD陶瓷电容; CODE: 8071629; COMPONENT_HIGH_MAX: 1.45MM; DEVICE: C2012X5R1E106KT000N1
C5 C8 C24 C30 = C_0: %182%%238%%182%%168%%185%%164%%215%%247%%181%%231%%209%%185%(V): 6.3; %195%%232%%202%%246%: SMD陶瓷电容-6.3V-220NF-+/-10%-X5R-0402-BT; %208%%161%%192%%224%%195%%251%%179%%198%: SMD陶瓷电容; CODE: 8070584; COMPONENT_HIGH_MAX: 0.55MM; DEVICE: GRM155R60J224KE01D
C35 C90 C116 C173 C179 C180 C187 C191 C281 = C_0: %182%%238%%182%%168%%185%%164%%215%%247%%181%%231%%209%%185%(V): 6.3; %195%%232%%202%%246%: SMD陶瓷电容-6.3V-10000NF-+/-20%-X5R-0603-BT,TS16949; %208%%161%%192%%224%%195%%251%%179%%198%: SMD陶瓷电容; CODE: 8070649; COMPONENT_HIGH_MAX: 0.9MM; DEVICE: C1608X5R0J106MT0A0E
C41 C43 C45 C46 C51 C53 C67-C69 C83 = C_0: %182%%238%%182%%168%%185%%164%%215%%247%%181%%231%%209%%185%(V): 16; %195%%232%%202%%246%: SMD陶瓷电容-16V-100NF-±10%-X7R-0402; %208%%161%%192%%224%%195%%251%%179%%198%: SMD陶瓷电容; CODE: 8070614; COMPONENT_HIGH_MAX: 0.6MM; DEVICE: RMEMK105BJ104KV_FR
C71 C72 = C_0: %182%%238%%182%%168%%185%%164%%215%%247%%181%%231%%209%%185%(V): 10; %195%%232%%202%%246%: SMD陶瓷电容-10V-2200NF-+/-10%-X5R-0603; %208%%161%%192%%224%%195%%251%%179%%198%: SMD陶瓷电容; CODE: 8070573; COMPONENT_HIGH_MAX: 0.9MM; DEVICE: GRM188R61A225KE34D
C76 C82 C84 C112 = C_0: %182%%238%%182%%168%%185%%164%%215%%247%%181%%231%%209%%185%(V): 50; %195%%232%%202%%246%: SMD陶瓷电容-50V-0.022NF-+/-5%-NP0-0402-BT; %208%%161%%192%%224%%195%%251%%179%%198%: SMD陶瓷电容; CODE: 8070545; COMPONENT_HIGH_MAX: 0.55MM; DEVICE: RMUMK105CG220JV_F
C91 C111 = C_0: %182%%238%%182%%168%%185%%164%%215%%247%%181%%231%%209%%185%(V): 50; %195%%232%%202%%246%: SMD陶瓷电容-50V-100NF-+/-10%-X7R-0603; %208%%161%%192%%224%%195%%251%%179%%198%: SMD陶瓷电容; CODE: 8070627; COMPONENT_HIGH_MAX: 0.95MM; DEVICE: C1608X7R1H104KT000N
C160 C161 C184 = CP_1: %182%%238%%182%%168%%185%%164%%215%%247%%181%%231%%209%%185%(V): 16; %195%%232%%202%%246%: 非固体SMD铝电容-16V-100UF-+/-20%-6.3*5.4MM-极性-105DEGC-1000H-片式,温度敏感器件-工艺耐温250DEGC,5S; %208%%161%%192%%224%%195%%251%%179%%198%: 非固体SMD铝电容; CODE: 8010269; COMPONENT_HIGH_MAX: 5.7MM; DEVICE: UWT1C101MCL1GB
C3 C7 C10 C11 C16 C18 C77 C94 C96 C152 C178 C188 C334 = C_0: %182%%238%%182%%168%%185%%164%%215%%247%%181%%231%%209%%185%(V): 10; %195%%232%%202%%246%: SMD陶瓷电容-10V-1000NF-+/-10%-X5R-0402-BT,TS16949; %208%%161%%192%%224%%195%%251%%179%%198%: SMD陶瓷电容; CODE: 8070612; COMPONENT_HIGH_MAX: 0.55MM; DEVICE: CV05X5R105K10AH
D6 = D2-3_D: %195%%232%%202%%246%: 瞬态抑制二极管-14.2V-15.8V-300W-0A-SOT-23; %208%%161%%192%%224%%195%%251%%179%%198%: 瞬态抑制二极管; CODE: 15040135; COMPONENT_HIGH_MAX: 1.21MM; DEVICE: SM12T1
J10 = PWC3_A_0: %195%%232%%202%%246%: 电源连接器-1PIN-50V-2A-弯式-公座-DC头,焊接; %208%%161%%192%%224%%195%%251%%179%%198%: 电源连接器; COMPONENT_HIGH_MAX: 11.1MM; DEVICE: DC2026_00
L2-L5 = SWPA4030S3R3MT_0: DEVICE: SWPA4030S3R3MT
L8 = SWPA5040S4R7MT_0: DEVICE: SWPA5040S6R8MT
LB6 LB9 = LB_v2: %195%%232%%202%%246%: EMI磁珠-±30%-600OHM-0.042OHM-3A-1210; %208%%161%%192%%224%%195%%251%%179%%198%: EMI磁珠; CODE: 10070007; COMPONENT_HIGH_MAX: 2.8MM; DEVICE: FCFBMH3225HM601NT
R6 R48 = R_0: %182%%238%%182%%168%%185%%166%%194%%202%(W): 0.06; %195%%232%%202%%246%: 片式厚膜电阻器-0.0625W-47000OHM-+/-5%-0402-ELOM; %208%%161%%192%%224%%195%%251%%179%%198%: 片式厚膜电阻器; %215%%232%%214%%181%%212%%202%%208%%237%%198%%171%%178%%238%: +/-5%; CODE: 7090819; COMPONENT_HIGH_MAX: 0.4MM; DEVICE: RC0402JR_0747K
R7 = R_0: %182%%238%%182%%168%%185%%166%%194%%202%(W): 0.06; %195%%232%%202%%246%: 片式厚膜电阻器-0.0625W-51000OHM-+/-1%-0402; %208%%161%%192%%224%%195%%251%%179%%198%: 片式厚膜电阻器; %215%%232%%214%%181%%212%%202%%208%%237%%198%%171%%178%%238%: +/-1%; CODE: 7091384; COMPONENT_HIGH_MAX: 0.4MM; DEVICE: RC_02W5102FT
R17 R101 = R_0: %182%%238%%182%%168%%185%%166%%194%%202%(W): 0.06; %195%%232%%202%%246%: 片式厚膜电阻器-0.0625W-14700OHM-+/-1%-0402; %208%%161%%192%%224%%195%%251%%179%%198%: 片式厚膜电阻器; %215%%232%%214%%181%%212%%202%%208%%237%%198%%171%%178%%238%: +/-1%; CODE: *; COMPONENT_HIGH_MAX: 0.4MM; DEVICE: RC_02W2402FT
R21 R23 = R_0: %182%%238%%182%%168%%185%%166%%194%%202%(W): 0.1; %195%%232%%202%%246%: 片式厚膜电阻器-0.1W-1000OHM-+/-1%-0603; %208%%161%%192%%224%%195%%251%%179%%198%: 片式厚膜电阻器; %215%%232%%214%%181%%212%%202%%208%%237%%198%%171%%178%%238%: +/-1%; CODE: 7092250; COMPONENT_HIGH_MAX: 0.5MM; DEVICE: RK73H1JTTD1001F
R47 = R_0: %182%%238%%182%%168%%185%%166%%194%%202%(W): 0.06; %195%%232%%202%%246%: 片式厚膜电阻器-0.0625W-13700OHM-+/- 1%-0402-供电专用-供电专用; %208%%161%%192%%224%%195%%251%%179%%198%: 片式厚膜电阻器; %215%%232%%214%%181%%212%%202%%208%%237%%198%%171%%178%%238%: +/- 1%; CODE: 7091435; COMPONENT_HIGH_MAX: 0.4MM; DEVICE: RC0402FR_0713K7L
R49 = R_0: %182%%238%%182%%168%%185%%166%%194%%202%(W): 0.06; %195%%232%%202%%246%: 片式厚膜电阻器-0.0625W-100000OHM-+/-1%-0402; %208%%161%%192%%224%%195%%251%%179%%198%: 片式厚膜电阻器; %215%%232%%214%%181%%212%%202%%208%%237%%198%%171%%178%%238%: +/-1%; CODE: 7090875; COMPONENT_HIGH_MAX: 0.4MM; DEVICE: RK73H1ETTP1003F
R52 R75 R100 R118 = R_0: %182%%238%%182%%168%%185%%166%%194%%202%(W): 0.06; %195%%232%%202%%246%: 片式厚膜电阻器-0.0625W-100000OHM-+/-5%-0402-BT; %208%%161%%192%%224%%195%%251%%179%%198%: 片式厚膜电阻器; %215%%232%%214%%181%%212%%202%%208%%237%%198%%171%%178%%238%: +/-5%; CODE: 7090831; COMPONENT_HIGH_MAX: 0.4MM; DEVICE: RK73B1ELTP104J
R53 = R_0: %182%%238%%182%%168%%185%%166%%194%%202%(W): 0.06; %195%%232%%202%%246%: 片式厚膜电阻器-0.0625W-15000OHM-+/-1%-0402-BT; %208%%161%%192%%224%%195%%251%%179%%198%: 片式厚膜电阻器; %215%%232%%214%%181%%212%%202%%208%%237%%198%%171%%178%%238%: +/-1%; CODE: 7091372; COMPONENT_HIGH_MAX: 0.4MM; DEVICE: RC_02W1502FT
R70 = R_0: %182%%238%%182%%168%%185%%166%%194%%202%(W): 0.06; %195%%232%%202%%246%: 片式厚膜电阻器-0.0625W-33000OHM-+/-5%-0402; %208%%161%%192%%224%%195%%251%%179%%198%: 片式厚膜电阻器; %215%%232%%214%%181%%212%%202%%208%%237%%198%%171%%178%%238%: +/-5%; CODE: 7090828; COMPONENT_HIGH_MAX: 0.4MM; DEVICE: RK73B1ELTP333J
R73 R142 R163 = R_0: %182%%238%%182%%168%%185%%166%%194%%202%(W): 0.06; %195%%232%%202%%246%: 片式厚膜电阻器-0.0625W-20000OHM-+/-1%-0402-TS16949; %208%%161%%192%%224%%195%%251%%179%%198%: 片式厚膜电阻器; %215%%232%%214%%181%%212%%202%%208%%237%%198%%171%%178%%238%: +/-1%; CODE: 7091374; COMPONENT_HIGH_MAX: 0.65MM; DEVICE: RC_02W2002FT
R95 = R_0: %182%%238%%182%%168%%185%%166%%194%%202%(W): 0.06; %195%%232%%202%%246%: 片式厚膜电阻器-0.0625W-100000OHM-+/-5%-0402-BT; %208%%161%%192%%224%%195%%251%%179%%198%: 片式厚膜电阻器; %215%%232%%214%%181%%212%%202%%208%%237%%198%%171%%178%%238%: +/-5%; CODE: 7090831; COMPONENT_HIGH_MAX: 0.37MM; DEVICE: RK73B1ELTP104J
R99 = R_0: %182%%238%%182%%168%%185%%166%%194%%202%(W): 0.06; %195%%232%%202%%246%: 片式厚膜电阻器-0.0625W-11300OHM-+/-1%-0402; %208%%161%%192%%224%%195%%251%%179%%198%: 片式厚膜电阻器; %215%%232%%214%%181%%212%%202%%208%%237%%198%%171%%178%%238%: +/-1%; CODE: 7090816; COMPONENT_HIGH_MAX: 0.4MM; DEVICE: RC0402FR_0711K3
R105 = R_0: %182%%238%%182%%168%%185%%166%%194%%202%(W): 0.1; %195%%232%%202%%246%: 片式厚膜电阻器-0.1W-7680OHM-+/-1%-0603; %208%%161%%192%%224%%195%%251%%179%%198%: 片式厚膜电阻器; %215%%232%%214%%181%%212%%202%%208%%237%%198%%171%%178%%238%: +/-1%; CODE: 7090826; COMPONENT_HIGH_MAX: 0.55MM; DEVICE: RC0603FR_077K68L
R110 = R_0: %182%%238%%182%%168%%185%%166%%194%%202%(W): 0.1; %195%%232%%202%%246%: 片式厚膜电阻器-0.1W-2000OHM-+/-5%-0603; %208%%161%%192%%224%%195%%251%%179%%198%: 片式厚膜电阻器; %215%%232%%214%%181%%212%%202%%208%%237%%198%%171%%178%%238%: +/-5%; CODE: 7090643; COMPONENT_HIGH_MAX: 0.55MM; DEVICE: RC0603JR_072K
R120 = R_0: %182%%238%%182%%168%%185%%166%%194%%202%(W): 0.06; %195%%232%%202%%246%: 片式厚膜电阻器-0.0625W-150000OHM-+/-1%-0402; %208%%161%%192%%224%%195%%251%%179%%198%: 片式厚膜电阻器; %215%%232%%214%%181%%212%%202%%208%%237%%198%%171%%178%%238%: +/-1%; CODE: 7090833; COMPONENT_HIGH_MAX: 0.4MM; DEVICE: RK73H1ELTP1503F
R131 = R_0: %182%%238%%182%%168%%185%%166%%194%%202%(W): 0.06; %195%%232%%202%%246%: 片式厚膜电阻器-0.0625W-22000OHM-+/-1%-0402; %208%%161%%192%%224%%195%%251%%179%%198%: 片式厚膜电阻器; %215%%232%%214%%181%%212%%202%%208%%237%%198%%171%%178%%238%: +/-1%; CODE: 7090798; COMPONENT_HIGH_MAX: 0.4MM; DEVICE: RK73H1ELTP2202F
R172 = R_0: %182%%238%%182%%168%%185%%166%%194%%202%(W): 0.06; %195%%232%%202%%246%: 片式厚膜电阻器-0.0625W-24900OHM-+/-1%-0402; %208%%161%%192%%224%%195%%251%%179%%198%: 片式厚膜电阻器; %215%%232%%214%%181%%212%%202%%208%%237%%198%%171%%178%%238%: +/-1%; CODE: 7091377; COMPONENT_HIGH_MAX: 0.4MM; DEVICE: RC_02W2492FT
R190 = R_0: %182%%238%%182%%168%%185%%166%%194%%202%(W): 0.06; %195%%232%%202%%246%: 片式厚膜电阻器-0.0625W-20OHM-+/-1%-0402; %208%%161%%192%%224%%195%%251%%179%%198%: 片式厚膜电阻器; %215%%232%%214%%181%%212%%202%%208%%237%%198%%171%%178%%238%: +/-1%; CODE: 7091308; COMPONENT_HIGH_MAX: 0.4MM; DEVICE: RC_02W200FT
R191 = R_0: %182%%238%%182%%168%%185%%166%%194%%202%(W): 0.1; %195%%232%%202%%246%: 片式厚膜电阻器-0.1W-40200OHM-+/-1%-0603; %208%%161%%192%%224%%195%%251%%179%%198%: 片式厚膜电阻器; %215%%232%%214%%181%%212%%202%%208%%237%%198%%171%%178%%238%: +/-1%; CODE: 7090935; COMPONENT_HIGH_MAX: 0.55MM; DEVICE: RK73H1JTTD4022F
U1 U15 = SY8009A: DEVICE: SY8089A_ETA3409
U11 U13 = SY8032
U18 = MP1470_1471A
C6 = C_0: %182%%238%%182%%168%%185%%164%%215%%247%%181%%231%%209%%185%(V): 10; %195%%232%%202%%246%: SMD陶瓷电容-10V-220NF-+/-10%-X7R-0603-供电专用-供电专用; %208%%161%%192%%224%%195%%251%%179%%198%: SMD陶瓷电容; CODE: 8070856; COMPONENT_HIGH_MAX: 0.9MM; DEVICE: C0603C224K8RAC7867
C133 = C_0: %182%%238%%182%%168%%185%%164%%215%%247%%181%%231%%209%%185%(V): 25; %195%%232%%202%%246%: SMD陶瓷电容-25V-1000NF-+/-10%-X7R-0603; %208%%161%%192%%224%%195%%251%%179%%198%: SMD陶瓷电容; CODE: 8070962; COMPONENT_HIGH_MAX: 0.9MM; DEVICE: CETMK107B7105KA_T
Q3 = FETP-GSD_3: %195%%232%%202%%246%: MOSFET-P沟道--30V--3A-98MOHM--20V-SOT23; %208%%161%%192%%224%%195%%251%%179%%198%: MOSFET; CODE: 15060138; COMPONENT_HIGH_MAX: 1.12MM; DEVICE: IRLML5203TR
Q4 = NPN-BEC_3: %195%%232%%202%%246%: 三极管-NPN-45V-100MA-225MW-200MV@100MA-SOT-23-180@2MA; %208%%161%%192%%224%%195%%251%%179%%198%: 三极管; CODE: 15050206; COMPONENT_HIGH_MAX: 1.26MM; DEVICE: BC847AE6327
Q8 Q13 = FETP-GSD_3: %195%%232%%202%%246%: MOSFET-P沟道--8V--3A-50MOHM--8V-SOT23; %208%%161%%192%%224%%195%%251%%179%%198%: MOSFET; CODE: 15060134; COMPONENT_HIGH_MAX: 1.11MM; DEVICE: IRLML6401TR
Q9 = NPN-BEC_2: %195%%232%%202%%246%: 三极管-NPN-45V-100MA-225MW-200MV@100MA-SOT-23-180@2MA; %208%%161%%192%%224%%195%%251%%179%%198%: 三极管; CODE: 15050206; COMPONENT_HIGH_MAX: 1.26MM; DEVICE: BC847AE6327
R30 R33 = R_0: %182%%238%%182%%168%%185%%166%%194%%202%(W): 0.06; %195%%232%%202%%246%: 片式厚膜电阻器-0.0625W-47000OHM-+/-1%-0402; %208%%161%%192%%224%%195%%251%%179%%198%: 片式厚膜电阻器; %215%%232%%214%%181%%212%%202%%208%%237%%198%%171%%178%%238%: +/-1%; CODE: 7090829; COMPONENT_HIGH_MAX: 0.4MM; DEVICE: RK73H1ELTP4702F
R98 R144 = R_0: %182%%238%%182%%168%%185%%166%%194%%202%(W): 0.06; %195%%232%%202%%246%: 片式厚膜电阻器-0.0625W-4700OHM-+/-5%-0402-BT; %208%%161%%192%%224%%195%%251%%179%%198%: 片式厚膜电阻器; %215%%232%%214%%181%%212%%202%%208%%237%%198%%171%%178%%238%: +/-5%; CODE: 7090793; COMPONENT_HIGH_MAX: 0.4MM; DEVICE: RK73B1ELTP472J
C42 C85 C88 C89 C95 C98 C99 C101 C102 C119 C122 C137 C146 = C_0: %182%%238%%182%%168%%185%%164%%215%%247%%181%%231%%209%%185%(V): 10; %195%%232%%202%%246%: SMD陶瓷电容-10V-100NF-+/-10%-X5R-0402; %208%%161%%192%%224%%195%%251%%179%%198%: SMD陶瓷电容; CODE: 8070561; COMPONENT_HIGH_MAX: 0.55MM; DEVICE: C0402C104K8PAC_7867
C9 C118 C248 C250 C251 = C_0: %182%%238%%182%%168%%185%%164%%215%%247%%181%%231%%209%%185%(V): 6.3; %195%%232%%202%%246%: SMD陶瓷电容-6.3V-2200NF-+/-20%-X5R-0402-TS16949; %208%%161%%192%%224%%195%%251%%179%%198%: SMD陶瓷电容; CODE: 8070667; COMPONENT_HIGH_MAX: 0.6MM; DEVICE: GRM155R60J225ME15D
C364 C365 = C_0: %182%%238%%182%%168%%185%%164%%215%%247%%181%%231%%209%%185%(V): 50; %195%%232%%202%%246%: SMD陶瓷电容-50V-0.03NF-+/-5%-NPO-0402; %208%%161%%192%%224%%195%%251%%179%%198%: SMD陶瓷电容; CODE: 8070604; COMPONENT_HIGH_MAX: 0.55MM; DEVICE: GRM1555C1H300J
J7 = WBC2X12: %195%%232%%202%%246%: 华为文档 00383947 - 得康（D2008－2×12A） A; CODE: 383947; COMPONENT_HIGH_MAX: 6.7MM; DEVICE: D2008_2X12A
J14 = HEAD2X2: %195%%232%%202%%246%: 插座-方孔-4PIN-双排弯式-2.54MM-5MM-3MM-THT; %208%%161%%192%%224%%195%%251%%179%%198%: 插座; CODE: 14200113; COMPONENT_HIGH_MAX: 8.25MM; DEVICE: WS254_04_H1_G1_D_B
LB7 LB8 LB11 LB17 LB18 LB20 LB31 LB35 = LB: %182%%238%%182%%168%%181%%231%%193%%247%: 0.25; %195%%232%%202%%246%: EMI磁珠-25%-220OHM-1OHM-0.25A-0402-900OHM TYP@1GHZ; %208%%161%%192%%224%%195%%251%%179%%198%: EMI磁珠; CODE: 10070030; COMPONENT_HIGH_MAX: 0.06MM; DEVICE: BLM15HB221SN1D
R1 = R_0: %182%%238%%182%%168%%185%%166%%194%%202%(W): 0.06; %195%%232%%202%%246%: 片式厚膜电阻器-0.0625W-1000000OHM-+/-1%-0402; %208%%161%%192%%224%%195%%251%%179%%198%: 片式厚膜电阻器; %215%%232%%214%%181%%212%%202%%208%%237%%198%%171%%178%%238%: +/-1%; CODE: 7090857; COMPONENT_HIGH_MAX: 0.4MM; DEVICE: RK73H1ETTP1004F
R14 R36 R37 = R_0: %182%%238%%182%%168%%185%%166%%194%%202%(W): 0.06; %195%%232%%202%%246%: 片式厚膜电阻器-0.0625W-0OHM-< 50MOHM-0402-1A-BT; %208%%161%%192%%224%%195%%251%%179%%198%: 片式厚膜电阻器; %215%%232%%214%%181%%212%%202%%208%%237%%198%%171%%178%%238%: < 50MOHM; CODE: 7090800; DEVICE: RC0402JR_070R
R16 = R_0: %182%%238%%182%%168%%185%%166%%194%%202%(W): 0.06; %195%%232%%202%%246%: 片式厚膜电阻器-0.0625W-22OHM-+/-5%-0402-BT; %208%%161%%192%%224%%195%%251%%179%%198%: 片式厚膜电阻器; %215%%232%%214%%181%%212%%202%%208%%237%%198%%171%%178%%238%: +/-5%; CODE: 7090803; COMPONENT_HIGH_MAX: 0.4MM; DEVICE: RC0402JR_0722RL
R26 R42 R86 R96 R130 = R_0: %182%%238%%182%%168%%185%%166%%194%%202%(W): 0.06; %195%%232%%202%%246%: 片式厚膜电阻器-0.0625W-10000OHM-+/-5%-0402-BT; %208%%161%%192%%224%%195%%251%%179%%198%: 片式厚膜电阻器; %215%%232%%214%%181%%212%%202%%208%%237%%198%%171%%178%%238%: +/-5%; CODE: 7090815; COMPONENT_HIGH_MAX: 0.4MM; DEVICE: RC_02W103JT
R56 R82 = R_0: %182%%238%%182%%168%%185%%166%%194%%202%(W): 0.06; %195%%232%%202%%246%: 片式厚膜电阻器-0.0625W-10000OHM-+/-5%-0402-BT; %208%%161%%192%%224%%195%%251%%179%%198%: 片式厚膜电阻器; %215%%232%%214%%181%%212%%202%%208%%237%%198%%171%%178%%238%: +/-5%; CODE: 7090815; DEVICE: RC_02W103JT
R40 R88 R91 = R_0: %182%%238%%182%%168%%185%%166%%194%%202%(W): 0.06; %195%%232%%202%%246%: 片式厚膜电阻器-0.0625W-1000OHM-+/-5%-0402-BT; %208%%161%%192%%224%%195%%251%%179%%198%: 片式厚膜电阻器; %215%%232%%214%%181%%212%%202%%208%%237%%198%%171%%178%%238%: +/-5%; CODE: 7090809; COMPONENT_HIGH_MAX: 0.4MM; DEVICE: RC0402JR_071KL
R173 = R_0: %182%%238%%182%%168%%185%%166%%194%%202%(W): 0.06; %195%%232%%202%%246%: 片式厚膜电阻器-0.0625W-10000OHM-+/-1%-0402-BT; %208%%161%%192%%224%%195%%251%%179%%198%: 片式厚膜电阻器; %215%%232%%214%%181%%212%%202%%208%%237%%198%%171%%178%%238%: +/-1%; CODE: 7090867; COMPONENT_HIGH_MAX: 0.4MM; DEVICE: RK73H1ETTP1002F
X2 = X_B_2: %195%%232%%202%%246%: 晶体谐振器-24MHZ; %208%%161%%192%%224%%195%%251%%179%%198%: 晶体谐振器; CODE: 12020151; COMPONENT_HIGH_MAX: 1MM; DEVICE: E5SB400000F15D11
C164 C182 C264 C270 C336 = C_0: %182%%238%%182%%168%%185%%164%%215%%247%%181%%231%%209%%185%(V): 16; %195%%232%%202%%246%: SMD陶瓷电容-16V-10NF-+/-10%-X7R-0402-BT,TS16949; %208%%161%%192%%224%%195%%251%%179%%198%: SMD陶瓷电容; CODE: 8070449; COMPONENT_HIGH_MAX: 0.55MM; DEVICE: GRM155R71C103KA01D
LB1 LB12 = LB_v2: %195%%232%%202%%246%: EMI磁珠-+/-25%-600OHM-0.65OHM-0.2A-402; %208%%161%%192%%224%%195%%251%%179%%198%: EMI磁珠; CODE: 10070013; COMPONENT_HIGH_MAX: 0.55MM; DEVICE: BLM15BD601SN1D
LB14 = LB_v2: %195%%232%%202%%246%: EMI磁珠-30OHM-0.05OHM-0.4A-0603-; %208%%161%%192%%224%%195%%251%%179%%198%: EMI磁珠; CODE: 10070003; COMPONENT_HIGH_MAX: 0.95MM; DEVICE: MGLB1608_030T_LF
R32 = R_0: %182%%238%%182%%168%%185%%166%%194%%202%(W): 0.06; %195%%232%%202%%246%: 片式厚膜电阻器-0.0625W-12000OHM-+/-1%-0402; %208%%161%%192%%224%%195%%251%%179%%198%: 片式厚膜电阻器; %215%%232%%214%%181%%212%%202%%208%%237%%198%%171%%178%%238%: +/-1%; CODE: 7090817; DEVICE: RC0402FR_0712K
R43 R44 R85 R87 = R_0: %182%%238%%182%%168%%185%%166%%194%%202%(W): 0.06; %195%%232%%202%%246%: 片式厚膜电阻器-0.0625W-270OHM-+/-5%-0402; %208%%161%%192%%224%%195%%251%%179%%198%: 片式厚膜电阻器; %215%%232%%214%%181%%212%%202%%208%%237%%198%%171%%178%%238%: +/-5%; CODE: 7090609; COMPONENT_HIGH_MAX: 0.4MM; DEVICE: RC0402JR_07270R
R55 = R_0: %182%%238%%182%%168%%185%%166%%194%%202%(W): 0.06; %195%%232%%202%%246%: 片式薄膜电阻器-0.0625W-200OHM-+/-0.1%-0402-+/-50PPM/DEGC; %208%%161%%192%%224%%195%%251%%179%%198%: 片式薄膜电阻器; %215%%232%%214%%181%%212%%202%%208%%237%%198%%171%%178%%238%: +/-0.1%; CODE: 7110054; COMPONENT_HIGH_MAX: 0.4MM; DEVICE: RN731ETTP2000B50
S10 = MSW-6A: %195%%232%%202%%246%: 微动开关-SPST-12VDC-0.05A-贴片-0.5MM-5.2*5.2*1.5MM-1,000,000; %208%%161%%192%%224%%195%%251%%179%%198%: 微动开关; COMPONENT_HIGH_MAX: 1.71MM; DEVICE: TMG_533_T_R
C20 = C_0: %182%%238%%182%%168%%185%%164%%215%%247%%181%%231%%209%%185%(V): 6.3; %195%%232%%202%%246%: SMD陶瓷电容-6.3V-10000NF-+/-10%-X7R-0805; %208%%161%%192%%224%%195%%251%%179%%198%: SMD陶瓷电容; CODE: 8070693; COMPONENT_HIGH_MAX: 1.4MM; DEVICE: GRM21BR70J106KE76L
C97 C100 = C_0: %182%%238%%182%%168%%185%%164%%215%%247%%181%%231%%209%%185%(V): 6.3; %195%%232%%202%%246%: SMD陶瓷电容-6.3V-470NF-+/-10%-X5R-0402; %208%%161%%192%%224%%195%%251%%179%%198%: SMD陶瓷电容; CODE: 8070625; COMPONENT_HIGH_MAX: 0.55MM; DEVICE: GRM155R60J474KE19D
R45 = R_0: %182%%238%%182%%168%%185%%166%%194%%202%(W): 0.06; %195%%232%%202%%246%: 片式厚膜电阻器-0.0625W-240OHM-+/- 1%-0402-BT; %208%%161%%192%%224%%195%%251%%179%%198%: 片式厚膜电阻器; %215%%232%%214%%181%%212%%202%%208%%237%%198%%171%%178%%238%: +/- 1%; CODE: 7091782; COMPONENT_HIGH_MAX: 0.4MM; DEVICE: RC0402FR_07240RL
U10 = HI3796MV100

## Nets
1V1_CORE: C51.1(A) C82.2(B) C90.1(A) C173.1(A) L3.2(B) LB11.1 LB12.2 LB31.1 R101.2(B) ; also on sheet 9
1V1_CPU: C35.1(A) C41.1(A) C76.2(B) C116.1(A) C161.1 L4.2(B) R53.2(B) ; also on sheet 9
1V5_DDR3: C20.1(A) C42.1(A) C68.1(A) C84.2(B) C94.1(A) C96.1(A) C97.1(A) C98.1(A) C99.1(A) C100.1(A) C101.1(A) C102.1(A) C137.1(A) C152.1(A) C179.1(A) C180.1(A) L2.2(B) R26.2(B) R120.2(B) U10.AA7(VDDIO_DDR_2) U10.AB6(VDDIO_DDR_3) U10.AB7(VDDIO_DDR_4) U10.AB8(VDDIO_DDR_5) U10.AB9(VDDIO_DDR_12) U10.AB10(VDDIO_DDR_6) U10.AB11(VDDIO_DDR_7) U10.AB12(VDDIO_DDR_8) U10.AB13(VDDIO_DDR_9) U10.AB14(VDDIO_DDR_10) U10.AB15(VDDIO_DDR_11) U10.AC5(VDDIO_DDR_24) U10.AC6(VDDIO_DDR_25) U10.AC7(VDDIO_DDR_26) U10.AC8(VDDIO_DDR_27) U10.AC12(VDDIO_DDR_33) U10.AD4(VDDIO_DDR_28) U10.AD5(VDDIO_DDR_29) U10.AD6(VDDIO_DDR_30) U10.AD7(VDDIO_DDR_31) U10.AE4(VDDIO_DDR_17) U10.AE5(VDDIO_DDR_18) U10.AE6(VDDIO_DDR_19) U10.N7(VDDIO_DDR_13) U10.N9(VDDIO_DDR_14) U10.P7(VDDIO_DDR_15) U10.P9(VDDIO_DDR_16) U10.R6(VDDIO_DDR_34) U10.R7(VDDIO_DDR_20) U10.T7(VDDIO_DDR_32) U10.U7(VDDIO_DDR_35) U10.V7(VDDIO_DDR_36) U10.W7(VDDIO_DDR_21) U10.W9(VDDIO_DDR_22) U10.Y7(VDDIO_DDR_1) U10.Y9(VDDIO_DDR_23) U10.Y11(VDDIO_DDR_CK_1) U10.Y12(VDDIO_DDR_CK_2) ; also on sheet 11 12
3V3: C67.1(A) C112.2(B) C187.1(A) C191.1(A) L5.2(B) Q13.2(S) R42.2(B) R88.2(B) R100.2(B) ; also on sheet 9 15 17
3V3_MOS: C88.1(A) C89.1(A) C348.1(A) J7.5(A5) LB1.2 LB7.2 LB8.2 LB14.1 LB17.1 LB18.1 LB20.1 LB35.1 Q13.3(D) R91.2(B) R96.2(B) U10.AA24(NF_DVDD3318_2) U10.AB24(NF_DVDD3318_3) U10.Y24(NF_DVDD3318_1) ; also on sheet 9 13 14 15 17 18 19 20 21 22
5V0: C2.1(A) C4.1(A) C6.1(A) C25.1(A) C26.1(A) C27.1(A) C46.1(A) C53.1(A) C59.1(A) C65.1(A) C69.1(A) C83.1(A) C114.1(A) C184.1 L8.2(B) Q8.2(S) R6.1(A) R48.1(A) R144.1(A) R191.2(B) U1.4(VIN) U11.4(VIN) U13.4(VIN) U15.4(VIN)
5V0_MOS: C347.1(A) J7.3(A3) Q8.3(D) ; also on sheet 14 16 19 21 22
12V0_MOS: C63.1(A) J7.1(A1) Q3.3(D) ; also on sheet 21
12V0_PWR: C44.1(A) C91.1(A) C111.1(A) C133.1(A) C160.1 LB6.2 Q3.2(S) R95.1(A) R98.1(A) R110.1(A) U18.3(VIN)
AVDD11_USB3: C16.1(A) C119.1(A) LB11.2 U10.AA19(AVDD11_VPTX0_USB3) U10.Y18(DVDD11_USB3) U10.Y19(AVDD11_VP_USB3)
AVDD33_ADAC: C188.1(A) LB35.2 U10.E22(AVDD33_ADAC)
AVDD33_USB2: C3.1(A) LB17.2 U10.U24(AVDD33_USB2)
AVDD33_USB3: C18.1(A) LB18.2 U10.AD20(AVDD33_USB3_2) U10.AD21(AVDD33_USB3_1)
GND: C2.2(B) C3.2(B) C4.2(B) C5.2(B) C7.2(B) C8.2(B) C9.2(B) C10.2(B) C11.2(B) C16.2(B) C18.2(B) C20.2(B) C24.2(B) C25.2(B) C26.2(B) C27.2(B) C30.2(B) C35.2(B) C41.2(B) C42.2(B) C43.2(B) C44.2(B) C45.2(B) C46.2(B) C51.2(B) C53.2(B) C59.2(B) C63.2(B) C65.2(B) C67.2(B) C68.2(B) C69.2(B) C71.2(B) C72.2(B) C77.2(B) C83.2(B) C85.2(B) C88.2(B) C89.2(B) C90.2(B) C91.2(B) C94.2(B) C95.2(B) C96.2(B) C97.2(B) C98.2(B) C99.2(B) C100.2(B) C101.2(B) C102.2(B) C111.2(B) C114.2(B) C116.2(B) C118.1(A) C119.2(B) C122.2(B) C137.2(B) C146.2(B) C152.2(B) C160.2 C161.2 C164.2(B) C173.2(B) C179.2(B) C180.2(B) C182.2(B) C184.2 C187.2(B) C188.2(B) C191.2(B) C248.2(B) C250.1(A) C251.2(B) C264.2(B) C270.2(B) C281.2(B) C334.2(B) C336.2(B) C347.2(B) C348.2(B) C364.2(B) C365.2(B) D6.2(C2) J3.1 J4.1 J5.1 J7.2(A2) J7.4(A4) J7.6(A6) J7.7(A7) J7.8(A8) J7.18(A18) J7.20(A20) J14.1(A1) J14.2(A2) J14.3(A3) J14.4(A4) LB9.2 M20.1(GND0) M20.2(GND1) M20.3(GND2) M20.4(GND3) M20.5(GND4) M20.6(GND5) M20.7(GND6) M20.8(GND7) M21.1(GND0) M21.2(GND1) M21.3(GND2) M21.4(GND3) M21.5(GND4) M21.6(GND5) M21.7(GND6) M21.8(GND7) M22.1(GND0) M22.2(GND1) M22.3(GND2) M22.4(GND3) M22.5(GND4) M22.6(GND5) M22.7(GND6) M22.8(GND7) M23.1(GND0) M23.2(GND1) M23.3(GND2) M23.4(GND3) M23.5(GND4) M23.6(GND5) M23.7(GND6) M23.8(GND7) Q4.2(E) Q9.2(E) R32.1(A) R43.2(B) R44.1(A) R45.2(B) R47.2(B) R52.2(B) R55.2(B) R56.1(A) R82.1(A) R85.2(B) R86.2(B) R87.1(A) R99.1(A) R105.2(B) R110.2(B) R130.1(A) R131.2(B) R173.2(B) S10.3 S10.4 S10.5 S10.6 U1.2(GND) U10.B4(AVSS_FE_4) U10.B25(AVSS_VDAC_1) U10.C4(AVSS_FE_1) U10.C6(AVSS_FE_2) U10.C7(AVSS_FE_3) U10.C8(AVSS_USB_3) U10.C10(AVSS_USB_4) U10.C16(AVSS_HDMITX_3) U10.C18(AVSS_HDMITX_7) U10.C22(AVSS_ADAC_1) U10.C24(AVSS_VDAC_3) U10.C25(AVSS_VDAC_4) U10.D4(AVSS_FE_5) U10.D6(AVSS_FE_6) U10.D7(AVSS_FE_7) U10.D8(AVSS_USB_5) U10.D10(AVSS_USB_6) U10.D16(AVSS_HDMITX_8) U10.D18(AVSS_HDMITX_4) U10.D22(AVSS_ADAC_2) U10.D24(AVSS_VDAC_2) U10.D25(AVSS_VDAC_6) U10.E5(AVSS_FE_9) U10.E8(AVSS_USB_8) U10.E9(AVSS_USB_2) U10.E15(AVSS_HDMITX_5) U10.E18(AVSS_HDMITX_6) U10.E23(AVSS_ADAC_4) U10.E24(AVSS_VDAC_5) U10.G8(AVSS_FE_10) U10.G12(AVSS_USB_1) U10.G17(AVSS_HDMITX_2) U10.G19(AVSS_VDAC_7) U10.H12(AVSS_USB_7) U10.H17(AVSS_HDMITX_1) U10.H18(AVSS_ADAC_3) U10.K11(AVSS_FE_8) U10.T22(AVSS_USB2_5) U10.T24(AVSS_USB2_1) U10.T25(AVSS_USB2_4) U10.T26(AVSS_USB2_2) U10.U22(AVSS_USB2_6) U10.U25(AVSS_USB2_3) U11.2(GND) U13.2(GND) U15.2(GND) U18.1(GND) X2.2(GND1) X2.4(GND2) ; also on sheet 9 10 11 12 13 14 15 16 17 18 19 20 21 22
3136_I2C_SCL: U10.D26(I2C0_SCL/GPIO1_6) ; also on sheet 20
3136_I2C_SDA: U10.C27(I2C0_SDA/GPIO1_7) ; also on sheet 20
3136_RSTN: U10.C28(DEM_RST/GPIO1_5) ; also on sheet 20
ADAC_VOUTL: U10.D23(ADAC_VOUTL) ; also on sheet 16
ADAC_VOUTR: U10.C23(ADAC_VOUTR) ; also on sheet 16
ADAC_VREF: C250.2(B) U10.G18(ADAC_VREFDAC)
CORE_CTRL: R23.2(B) U10.E27(GPIO2_6/PMC_PWM0/I2C2_SCL)
CPU_CTRL: R21.2(B) U10.E28(GPIO2_7/PMC_PWM1/I2C2_SDA)
CVBS: U10.A25(VDAC_0) ; also on sheet 18
DDR_ADDR0: U10.AF13(DDR_ADDR9) ; also on sheet 11 12
DDR_ADDR1: U10.AE12(DDR_ADDR11) ; also on sheet 11 12
DDR_ADDR2: U10.AD15(DDR_ADDR2) ; also on sheet 11 12
DDR_ADDR3: U10.AH15(DDR_ADDR0) ; also on sheet 11 12
DDR_ADDR4: U10.AD13(DDR_ADDR15) ; also on sheet 11 12
DDR_ADDR5: U10.AE16(DDR_ADDR13) ; also on sheet 11 12
DDR_ADDR6: U10.AF11(DDR_ADDR6) ; also on sheet 11 12
DDR_ADDR7: U10.AG15(DDR_ADDR3) ; also on sheet 11 12
DDR_ADDR8: U10.AG12(DDR_ADDR8) ; also on sheet 11 12
DDR_ADDR9: U10.AE17(DDR_ADDR5) ; also on sheet 11 12
DDR_ADDR10: U10.AE9(DDR_ADDR10) ; also on sheet 11 12
DDR_ADDR11: U10.AG10(DDR_ADDR12) ; also on sheet 11 12
DDR_ADDR12: U10.AE11(DDR_ADDR1) ; also on sheet 11 12
DDR_ADDR13: U10.AF17(DDR_ADDR7) ; also on sheet 11 12
DDR_ADDR14: U10.AF12(DDR_ADDR14) ; also on sheet 11 12
DDR_ADDR15: U10.AD11(DDR_ADDR4) ; also on sheet 11 12
DDR_BA0: U10.AH16(DDR_BA0) ; also on sheet 11 12
DDR_BA1: U10.AF10(DDR_BA1) ; also on sheet 11 12
DDR_BA2: U10.AE13(DDR_BA2) ; also on sheet 11 12
DDR_CASN: U10.AE15(DDR_CAS) ; also on sheet 11 12
DDR_CKE: R130.2(B) U10.AD10(DDR_CKE) ; also on sheet 11 12
DDR_CLK1N: R37.1(A) ; also on sheet 11 12
DDR_CLK1P: R36.1(A) ; also on sheet 11 12
DDR_CSN: U10.AH13(DDR_CS0) ; also on sheet 11 12
DDR_DM0: U10.R4(DDR_DM0) ; also on sheet 11
DDR_DM1: U10.T5(DDR_DM1) ; also on sheet 11
DDR_DM2: U10.AF1(DDR_DM2) ; also on sheet 12
DDR_DM3: U10.AE2(DDR_DM3) ; also on sheet 12
DDR_DQ0: U10.N4(DDR_DQ0) ; also on sheet 11
DDR_DQ1: U10.V1(DDR_DQ1) ; also on sheet 11
DDR_DQ2: U10.N1(DDR_DQ2) ; also on sheet 11
DDR_DQ3: U10.W3(DDR_DQ3) ; also on sheet 11
DDR_DQ4: U10.N5(DDR_DQ4) ; also on sheet 11
DDR_DQ5: U10.Y3(DDR_DQ5) ; also on sheet 11
DDR_DQ6: U10.N2(DDR_DQ6) ; also on sheet 11
DDR_DQ7: U10.W2(DDR_DQ7) ; also on sheet 11
DDR_DQ8: U10.U4(DDR_DQ8) ; also on sheet 11
DDR_DQ9: U10.R2(DDR_DQ9) ; also on sheet 11
DDR_DQ10: U10.U5(DDR_DQ10) ; also on sheet 11
DDR_DQ11: U10.P3(DDR_DQ11) ; also on sheet 11
DDR_DQ12: U10.V4(DDR_DQ12) ; also on sheet 11
DDR_DQ13: U10.P4(DDR_DQ13) ; also on sheet 11
DDR_DQ14: U10.W4(DDR_DQ14) ; also on sheet 11
DDR_DQ15: U10.P5(DDR_DQ15) ; also on sheet 11
DDR_DQ16: U10.AA5(DDR_DQ16) ; also on sheet 12
DDR_DQ17: U10.AF6(DDR_DQ17) ; also on sheet 12
DDR_DQ18: U10.AA2(DDR_DQ18) ; also on sheet 12
DDR_DQ19: U10.AG6(DDR_DQ19) ; also on sheet 12
DDR_DQ20: U10.Y5(DDR_DQ20) ; also on sheet 12
DDR_DQ21: U10.AH7(DDR_DQ21) ; also on sheet 12
DDR_DQ22: U10.AA3(DDR_DQ22) ; also on sheet 12
DDR_DQ23: U10.AF7(DDR_DQ23) ; also on sheet 12
DDR_DQ24: U10.AF5(DDR_DQ24) ; also on sheet 12
DDR_DQ25: U10.AB1(DDR_DQ25) ; also on sheet 12
DDR_DQ26: U10.AG4(DDR_DQ26) ; also on sheet 12
DDR_DQ27: U10.AB3(DDR_DQ27) ; also on sheet 12
DDR_DQ28: U10.AH3(DDR_DQ28) ; also on sheet 12
DDR_DQ29: U10.AA4(DDR_DQ29) ; also on sheet 12
DDR_DQ30: U10.AG3(DDR_DQ30) ; also on sheet 12
DDR_DQ31: U10.AB4(DDR_DQ31) ; also on sheet 12
DDR_DQS0N: U10.T1(DDR_DQSB0) ; also on sheet 11
DDR_DQS0P: U10.T2(DDR_DQS0) ; also on sheet 11
DDR_DQS1N: U10.U3(DDR_DQSB1) ; also on sheet 11
DDR_DQS1P: U10.U2(DDR_DQS1) ; also on sheet 11
DDR_DQS2N: U10.AC2(DDR_DQSB2) ; also on sheet 12
DDR_DQS2P: U10.AC3(DDR_DQS2) ; also on sheet 12
DDR_DQS3N: U10.AD2(DDR_DQSB3) ; also on sheet 12
DDR_DQS3P: U10.AD1(DDR_DQS3) ; also on sheet 12
DDR_ODT: U10.AG16(DDR_ODT0) ; also on sheet 11 12
DDR_PLL: C11.1(A) C264.1(A) C270.1(A) LB7.1 U10.T9(AVDD_DDRPLL1) U10.Y14(AVDD_DDRPLL2)
DDR_RASN: U10.AG17(DDR_RAS) ; also on sheet 11 12
DDR_RESETN: R26.1(A) U10.AG14(DDR_RESETN) ; also on sheet 11 12
DDR_WEN: U10.AE14(DDR_WE) ; also on sheet 11 12
DEMOD0_RESTN: J7.10(A10) U10.L28(JTAG_TDI/TSI0_D4/TSI0_SYNC/GPIO0_7)
DEMOD0_SCL: J7.23(A23) U10.G27(GPIO1_4/TSI0_VALID)
DEMOD0_SDA: J7.24(A24) U10.G28(GPIO1_3/TSI0_CLK)
FE_1V1: C248.1(A) U10.K12(AVDD11_FE_DECAP)
FE_3V3: C7.1(A) LB8.1 U10.E6(AVDD33_FE_2) U10.E7(AVDD33_FE_1)
FE_REXT: R173.1(A) U10.G9(FE_REXT)
FUNC_SEL: R42.1(A) U10.AF26(FUNC_SEL)
HDMI_TX0N: U10.D17(HDMI_TX0N) ; also on sheet 19
HDMI_TX0P: U10.C17(HDMI_TX0P) ; also on sheet 19
HDMI_TX1N: U10.B16(HDMI_TX1N) ; also on sheet 19
HDMI_TX1P: U10.A16(HDMI_TX1P) ; also on sheet 19
HDMI_TX2N: U10.D15(HDMI_TX2N) ; also on sheet 19
HDMI_TX2P: U10.C15(HDMI_TX2P) ; also on sheet 19
HDMI_TX_1V1: C95.1(A) C164.1(A) C251.1(A) C281.1(A) LB12.1 U10.G16(AVCC11_HDMITX_2) U10.H16(AVCC11_HDMITX_1)
HDMI_TX_3V3: C77.1(A) C122.1(A) LB1.1 U10.E16(AVDD33_HDMITX_1) U10.E17(AVDD33_HDMITX_2)
HDMI_TX_CEC: U10.A20(GPIO4_7/HDMITX_CEC) ; also on sheet 19
HDMI_TX_HOTPLUG: U10.D21(GPIO4_6/HDMITX_HOTPLUG) ; also on sheet 19
HDMI_TX_SCL: U10.B20(GPIO4_5/HDMITX_SCL) ; also on sheet 19
HDMI_TX_SDA: U10.C21(GPIO4_4/HDMITX_SDA) ; also on sheet 19
HDMI_TXCN: U10.B18(HDMI_TXCN) ; also on sheet 19
HDMI_TXCP: U10.A18(HDMI_TXCP) ; also on sheet 19
IR_IN: U10.AG24(GPIO5_1/IR_IN) ; also on sheet 15
JTAG_SEL: R96.1(A) U10.F26(JTAG_SEL)
LED0_BASE: U10.C2(GPIO2_2/FE_LED_BASE) ; also on sheet 17
LED0_LINK_ACT: U10.B1(GPIO2_1/FE_LED_ACT) ; also on sheet 17
LED_CLK: U10.AH23(GPIO5_6/LED_CLK) ; also on sheet 15
LED_DATA: U10.AG23(GPIO5_5/LED_DATA) ; also on sheet 15
LED_KEY0: U10.AF23(GPIO5_2/LED_KEY0) ; also on sheet 15
MUTE_CTRL: U10.A22(MUTE_CTRL/GPIO4_3) ; also on sheet 16
NF_ALE_EMMC_PWREN: U10.W26(NF_ALE/SDIO1_CARD_POWER_EN/GPIO0_1) ; also on sheet 13
NF_CLE: U10.V26(NF_CLE/SDIO1_CWPR/GPIO0_2) ; also on sheet 13
NF_CSN0_EMMC_CMD: U10.V28(NF_CSN0/SDIO1_CCMD) ; also on sheet 13
NF_DQ0_EMMC_D0: U10.Y28(EBI_DQ0/SDIO1_CDATA0) ; also on sheet 13
NF_DQ1_EMMC_D1: U10.Y26(EBI_DQ1/SDIO1_CDATA1) ; also on sheet 13
NF_DQ2_EMMC_D2: U10.AA26(EBI_DQ2/SDIO1_CDATA2) ; also on sheet 13
NF_DQ3_EMMC_D3: U10.AA25(EBI_DQ3/SDIO1_CDATA3) ; also on sheet 13
NF_DQ4_EMMC_D4: U10.AB28(EBI_DQ4/SDIO1_CDATA4) ; also on sheet 13
NF_DQ5_EMMC_D5: U10.AB26(EBI_DQ5/SDIO1_CDATA5) ; also on sheet 13
NF_DQ6_EMMC_D6: U10.AC26(EBI_DQ6/SDIO1_CDATA6) ; also on sheet 13
NF_DQ7_EMMC_D7_BOOT_SEL0: R86.1(A) U10.AC25(EBI_DQ7/SDIO1_CDATA7/BOOT_SEL0) ; also on sheet 13
NF_RDY0_EMMC_RST: U10.U26(NF_RDY0/SDIO1_RST) ; also on sheet 13
NF_REN_EMMC_CLK: U10.W25(NF_REN/SDIO1_CCLK_OUT) ; also on sheet 13
NF_WEN_EMMC_DET: R56.2(B) U10.V27(NF_WEN/SDIO1_CARD_DETECT/GPIO0_0) ; also on sheet 13
RX+_PHY0: U10.B6(FE_RXP) ; also on sheet 17
RX-_PHY0: U10.A6(FE_RXN) ; also on sheet 17
SDIO0_CARD_DETECT: U10.J2(SDIO0_CARD_DETECT/GPIO3_6) ; also on sheet 15
SDIO0_CCLK_OUT: R16.1(A) ; also on sheet 15
SDIO0_CCMD: U10.F2(SDIO0_CCMD/GPIO3_3) ; also on sheet 15
SDIO0_CDATA0: U10.E3(SDIO0_CDATA0/GPIO3_1) ; also on sheet 15
SDIO0_CDATA1: U10.D3(SDIO0_CDATA1/GPIO3_0) ; also on sheet 15
SDIO0_CDATA2: U10.H3(SDIO0_CDATA2/GPIO3_5) ; also on sheet 15
SDIO0_CDATA3: U10.G3(SDIO0_CDATA3/GPIO3_4) ; also on sheet 15
SDIO0_CWPR: R82.2(B) U10.C1(SDIO0_CWPR/GPIO2_3)
SDIO0_PWREN: U10.J1(SDIO0_CARD_POWER_EN/GPIO3_7) ; also on sheet 15
SDIO_3318: C118.2(B) U10.K4(SDIO_DVDD18_DECAP_2) U10.K5(SDIO_DVDD18_DECAP_1) ; also on sheet 15
SIM0_CLK: U10.AH26(SIM0_CLK) ; also on sheet 22
SIM0_DATA: U10.AG25(SIM0_DATA) ; also on sheet 22
SIM0_DET: U10.AH25(SIM0_DET) ; also on sheet 22
SIM0_PWREN: U10.AG26(SIM0_PWREN) ; also on sheet 22
SIM0_RST: U10.AF24(SIM0_RST) ; also on sheet 22
SPDIF_OUT_BOOT_SEL1: R91.1(A) U10.B22(SPDIF_OUT/GPIO4_2/BOOT_SEL1) ; also on sheet 16
STANDBY_PWROFF: R30.1(A) R33.1(A) R73.1(A) R88.1(A) R142.1(A) R163.1(A) U10.AG27(GPIO5_0/STANDBY_PWROFF)
TSI0_CLK: J7.19(A19) U10.N27(JTAG_TRSTN/TSI0_D6/TSI0_CLK/GPIO0_5)
TSI0_D0: J7.17(A17) U10.N28(JTAG_TMS/TSI0_D7/GPIO0_4)
TSI0_VALID: J7.21(A21) U10.M26(JTAG_TCK/TSI0_D5/TSI0_VALID/GPIO0_6)
TSI1_CLK: U10.K28(GPIO1_0/TSI0_D2/TSI1_CLK) ; also on sheet 20
TSI1_D0: U10.L27(JTAG_TDO/TSI0_D3/TSI1_D7/GPIO2_0) ; also on sheet 20
TSI1_SYNC: U10.H26(GPIO1_2/TSI0_D0/TSI1_SYNC) ; also on sheet 20
TSI1_VALID: U10.J27(GPIO1_1/TSI0_D1/TSI1_VALID) ; also on sheet 20
TX+_PHY0: U10.D5(FE_TXP) ; also on sheet 17
TX-_PHY0: U10.C5(FE_TXN) ; also on sheet 17
UART0_RXD: U10.AF28(UART1_RXD/UART0_RXD) ; also on sheet 17
UART0_TXD: U10.AF27(UART1_TXD/UART0_TXD) ; also on sheet 17
USB0_DM: U10.A8(USB0_DM) ; also on sheet 14
USB0_DP: U10.B8(USB0_DP) ; also on sheet 14
USB01_1V1: C334.1(A) C336.1(A) LB31.2 U10.H11(AVCC11_USB)
USB01_3V3: C10.1(A) C182.1(A) LB20.2 U10.E10(AVDD33_USB)
USB1_DM: U10.C9(USB1_DM) ; also on sheet 14
USB1_DP: U10.D9(USB1_DP) ; also on sheet 14
USB2_DM: U10.T27(USB2_DM) ; also on sheet 14
USB2_DP: U10.T28(USB2_DP) ; also on sheet 14
USB2_RBI: R43.1(A) R85.1(A) U10.R25(USB2_RBIAS)
USB3_DM: U10.AH19(USB3_DM) ; also on sheet 14
USB3_DP: U10.AG19(USB3_DP) ; also on sheet 14
USB3_REXT: R55.1(A) U10.AD18(USB3_REXT)
USB3_RXN: U10.AG21(USB3_RXN) ; also on sheet 14
USB3_RXP: U10.AH21(USB3_RXP) ; also on sheet 14
USB3_TXN: U10.AE20(USB3_TXN) ; also on sheet 14
USB3_TXP: U10.AF20(USB3_TXP) ; also on sheet 14
USB_BOOT: R40.2(B) U10.A27(USB_BOOT/GPIO2_5)
USBRBIAS: R44.2(B) R87.2(B) U10.G11(USBRBIAS)
VDAC_3V3: C9.1(A) C85.1(A) LB14.2 U10.F23(AVDD33_VDAC_1) U10.F24(AVDD33_VDAC_2)
VDAC_IREF: R32.2(B) U10.B24(VDAC_IREF)
XIN: C364.1(A) R1.2(B) U10.AD27(XIN) X2.1
XOUT: R1.1(A) R14.1(A) U10.AD28(XOUT)
N17710: R45.1(A) U10.AC17(DDR_ZCOMP)
N17928: R37.2(B) U10.AG8(DDR_CKB1)
N17932: R36.2(B) U10.AF8(DDR_CK1)
N19711: C146.1(A) R40.1(A) S10.1 S10.2
N21338: C365.1(A) R14.2(B) X2.3
N22120: C6.2(B) Q8.1(G) Q13.1(G) R118.1(A)
N22134: Q4.3(C) R118.2(B) R144.2(B)
N22144: Q9.3(C) R75.2(B) R98.2(B)
N22154: C133.2(B) Q3.1(G) R75.1(A)
N22170: Q4.1(B) R33.2(B)
N22174: Q9.1(B) R30.2(B)
N23352: R17.2(B) R49.1(A)
N23384: C5.1(A) R142.2(B) U13.1(EN)
N23670: R190.1(A) U18.6(BST)
N23678: C178.2(B) L8.1(A) U18.2(SW)
N23686: L3.1(A) U13.3(LX)
N23690: L2.1(A) U15.3(LX)
N23694: C84.1(A) R52.1(A) R120.1(A) U15.5(FB)
N23706: C45.1(A) C72.1(A) R23.1(A) R49.2(B)
N23718: R7.1(A) R70.2(B)
N23722: L4.1(A) U11.3(LX)
N23726: C76.1(A) R53.1(A) R70.1(A) R99.2(B) U11.6(FB)
N23746: C43.1(A) C71.1(A) R7.2(B) R21.1(A)
N23758: J10.1(A1) J10.3(A3) LB9.1
N23770: C8.1(A) R73.2(B) U11.1(EN)
N23812: D6.1(C1) J10.2(A2) LB6.1
N23822: R95.2(B) U18.5(EN)
N23826: C178.1(A) R190.2(B)
N23832: R172.1(A) U18.4(FB)
N23836: R105.1(A) R172.2(B) R191.1(A)
N23844: C112.1(A) R100.1(A) R131.1(A) U1.5(FB)
N23856: L5.1(A) U1.3(LX)
N23860: C24.1(A) R48.2(B) U1.1(EN)
N23868: C30.1(A) R6.2(B) R163.2(B) U15.1(EN)
N23886: C82.1(A) R17.1(A) R47.1(A) R101.1(A) U13.6(FB)
N227705: R16.2(B) U10.E1(SDIO0_CCLK_OUT/GPIO3_2)

Not connected (* = marked no-connect by the designer): D6 3(A); ID1 1; ID2 1; ID3 1; ID4 1; ID5 1; ID6 1; J7 9(A9) 11(A11) 12(A12) 13(A13) 14(A14) 15(A15) 16(A16) 22(A22); M20 9(HOLE); M21 9(HOLE); M22 9(HOLE); M23 9(HOLE); U10 A10(I2S0_DOUT0/GPIO6_5) A13(SPI_SCLK/GPIO0_3/UART2_CTSN) A14(SPI_CSN1/GPIO6_1) AG9(DDR_CKB0) AH9(DDR_CK0) B10(I2S0_WS/GPIO6_4) B13(SPI_CSN0/GPIO6_0/UART2_RTSN/I2C1_SDA) C11(I2S0_MCLK/GPIO6_6) C12(SLIC_RST/GPIO6_2) C13(SPI_SDO/GPIO4_0/UART2_RXD) D11(I2S0_DIN0/GPIO6_7) D12(I2S0_BCLK/GPIO6_3) D13(SPI_SDI/GPIO4_1/UART2_TXD/I2C1_SCL); U11 5(PG); U13 5(PG)

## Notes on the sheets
sheet 1
- PAGE1
- Title Page
- PAGE2
- Power Tree
- PAGE3
- Block Diagram
- PAGE4
- Power on board
- PAGE5
- Power Ctrl
- Hi3796MDMO1A
- PAGE6
- Unit 1 of Hi3796M(NAND/I2S+SPI/TSI/IR/SDIO/XTAL/FE)
- PAGE7
- Unit 2 of Hi3796M(USB2.0/USB3.0/HDMI TX/DAC/UART)
- PAGE8
- Unit 3 of Hi3796M(DDR3)
- PAGE9
- Unit 4 of Hi3796M(POWER)
- VER_A
- PAGE10
- Unit 5 of Hi3796M(VSS)
- PAGE11
- DDRA
- PAGE12
- DDRB
- PAGE13
- NAND FLASH/EMMC
- PAGE14
- USB2.0/USB3.0/WIFI
- Hi3796MV100 DEMO Board
- PAGE15
- SD CARD/IR
- PAGE16
- Audio Output
- 4 layers PCB with 2x DDR3 16bit
- PAGE17
- FE PHY/UART
- PAGE18
- VDAC OUTPUT
- Hi3796MDMO1A VER.A_V1.0.0.0
- PAGE19
- HDMI TX
- PAGE20
- Hi3136V100
- PAGE21
- AV2012+LNB
- PAGE22
- SCI CARD
sheet 2
- Power Tree
- PMOS
- 5V0_MOS
- 1000mA
- AUDIO AMP
- HDMI
- SPDIF
- 5V0
- 12V
- DCDC
- 5V_VBUS
- USB x 3
- SW x 3
- 3V3
- 20mA
- 3V3 Standby
- DCDC
- IR & LED
- 3V3_MOS
- 150mA
- CHIP
- I/O
- PMOS
- USB
- SD CARD
- VDAC
- NAND FLASH/eMMC
- ADAC
- FE
- HDMI
- PLL
- DCDC
- 1V1_CORE
- 2000mA
- CORE
- USB
- VDAC
- DCDC
- 1V1_CPU
- 3000mA
- CPU
- HDMI
- FE
- PLL
- DCDC
- 1V5_DDR3
- 1000mA
- DDR PHY
- DDR
sheet 3
- Block Diagram
- 12V0
- ETH
- HDMI
- SPDIF
- L/R/CVBS
- Tuner
- DVB-S
- Sub Board
- 24Pin Connect
- 3136
- USB2.0
- USB2.0
- USB2.0
- DDRA
- To
- Hi3796MV100
- WiFi
- USB3.0
- DDRB
- eMMC
- TF CARD
- IR/LED/KEY
- SIM
sheet 4
- 12V PLUG-IN
- CPU POWER
- Vcpu=0.9V-1.5V@3A
- 5V POWER
- VOUT=0.804*(1+40.2K/7.68K)=5.01V @3A
- Close to Hi3796MV100
- CORE POWER
- 3V3 POWER
- VOUT=0.6*(1+100K/22K)=3.327V @1A
- Vcore=0.9V-1.32V@3A
- DDR POWER
- VOUT=0.6*(1+150K/100K)=1.5V @1.5A
- Close to Hi3796MV100
sheet 5
- Power Ctrl
- S
- D
- S
- D
- S
- D
- G
- G
- G
- STANDBY_PWROFF
- 0
- Power Off
- 1
- Power On
sheet 6
- Unit 1 of Hi3796MV100(NAND/SDIO/SPI+I2S/FE/SIM/FP/Sys)
- 1%
- Just For TF CARD
- BOOT DEVICE SEL
- BOOT_SEL[1:0]
- BOOT_SEL0
- PU
- 01:NAND Flash
- System Oscillator
- BOOT_SEL1
- PD
- 11:eMMC
- PD
- PU
- ** FE PHY Design guideline **
- A.routing
- 1.Route as 100 Ohm differential impedance.
- 2.Differential pairs should be routed on TOP layer only.
- 3.Differential pairs should be separated from other traces by GND .
- B.trace length
- 1.The length for the differential pairs should be less than 5 inches.
- 2.Match trace length of RX and TX differential pairs, 10 mils max within a pair.
- C.component selection
- 1.REXT resistor should be 10K ohm +/-1%.
- 2.ESD components are suggested for ports protection,
- Put between Hi3796MV100 and transformer.
sheet 7
- Unit 2 of Hi3796MV100(JTAG/USB2.0/HDMI TX/DAC/I2S/SPI/UART)
- 1%
- ** Audio & Video Design guideline **
- A.VIDEO
- 1.VIDEO REXT resistor should be 12K +/-1% precision.
- 2.REXT/COMP should be traced as short as possible,
- and isolated from all other traces.
- B.AUDIO
- 1.VREF should be traced as short as possible,
- and isolated from all other traces.
- 135ohm
- 1%
- 1%
- 1%
- ** USB Design guideline **
- A.routing
- 1.Route as 90 Ohm differential impedance.
- 2.Differential pairs should be routed on TOP layer only.
- 3.Differential pairs should be separated from other traces by GND .
- B.trace length
- 1.The length for the differential pairs should be less than 5 inches.
- 2.Match trace length of DP and DM differential pairs, 10 mils max within a pair.
- C.component selection
- 1.USB2.0 REXT resistor should be 135 ohm +/-1% and USB3.0 200 ohm +/-1%.
- 2.ESD components are suggested for ports protection.
- 3.Equivalent capacitance of ESD component should be < 1.5pF.
sheet 8
- Unit 3 of Hi3796MV100(DDR)
- 1%
- Close to Hi3796MV100
- ** DDR Design guideline **
- A.general suggestion
- 1.Hi3796MV100 supports up to 2GB DDR3.
- 2.DDR chip and DDR controller both need at least one 10uF decoupling ceramic capacitor.
- 3.The ciruit of DDR_VREF_CA and DDR_VREF_DQ must be independent
- 4. 3V3 DDRPLL is needed.
- B.Layout suggestion
- 1. Please copy hisilicon demo board completely
